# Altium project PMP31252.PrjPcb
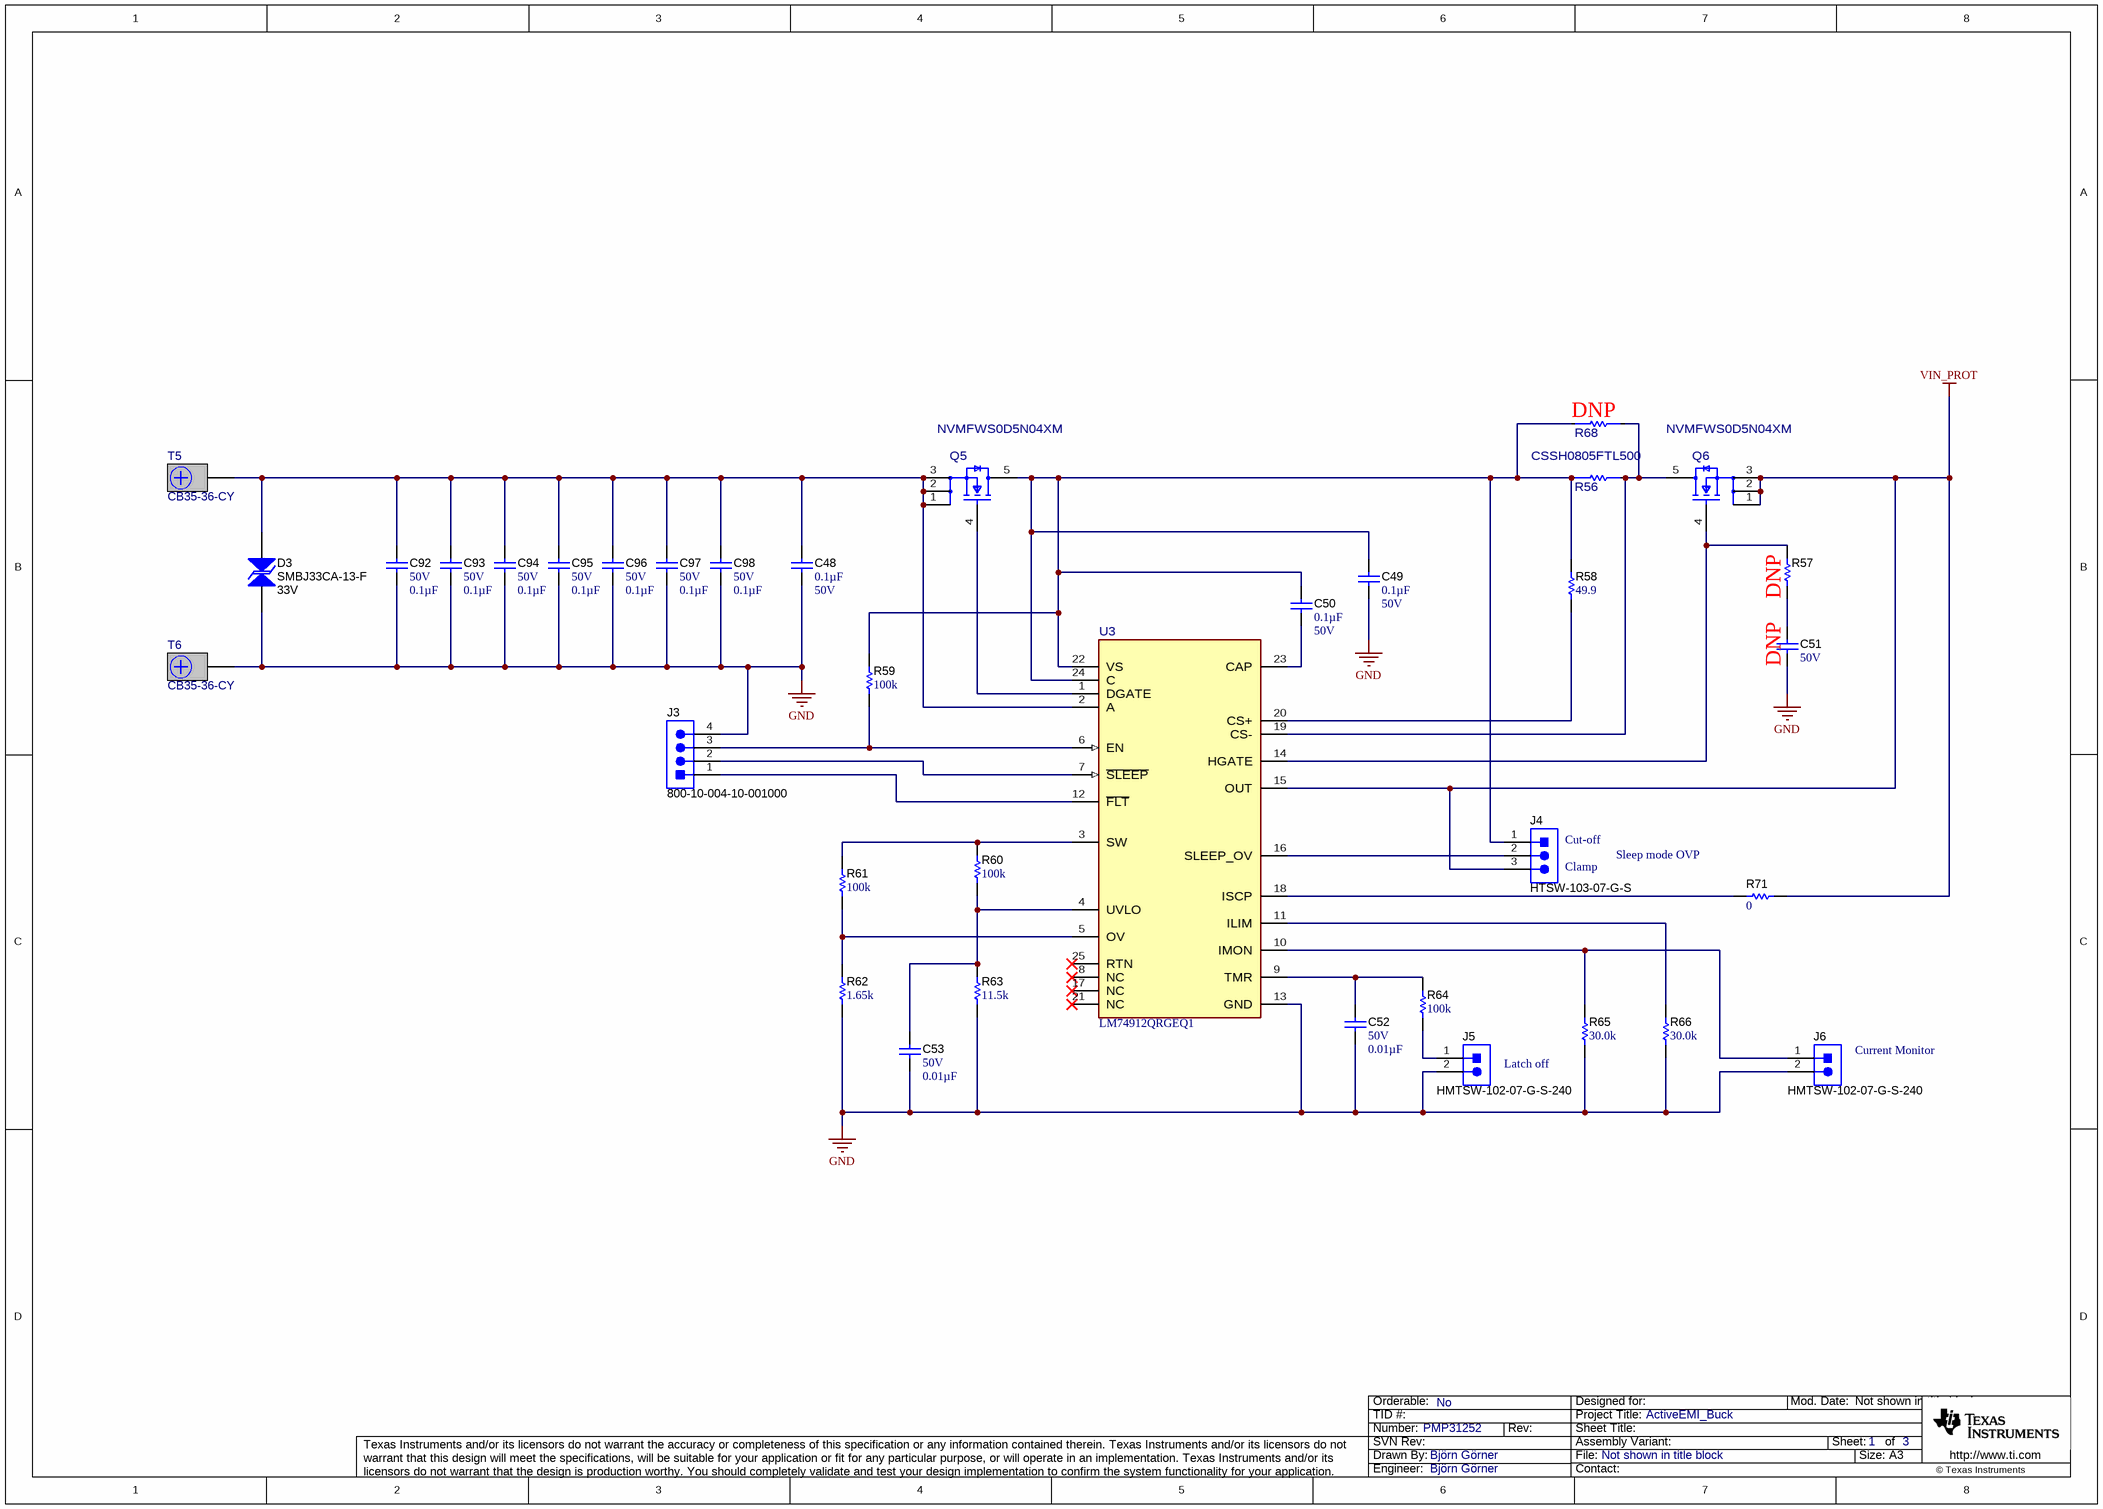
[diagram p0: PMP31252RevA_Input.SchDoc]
DrawnBy: Björn Görner; EVM_orderable: No; PRJ_Engineer: Björn Görner; PRJ_Number: E1; PRJ_Number: PMP31252; PRJ_Title: ActiveEMI_Buck
3 sheets, 218 parts. Net scope: global (net labels, ports and power ports of the same name join across sheets).
Board file: PMP31252.PcbDoc
Sheets:
  PMP31252RevA_Input.SchDoc
  PMP31252RevA_M.SchDoc
  PMP31252RevA_S.SchDoc

## Sheet PMP31252RevA_Input.SchDoc
size A3; Date: Not shown in title block; ApprovedBy: Not shown in title block; CheckedBy: Not shown in title block; Author: Not shown in title block; CompanyName: Not shown in title block; Engineer: Not shown in title block; Organization: Not shown in title block; Address1: Not shown in title block; Address2: Not shown in title block; Address3: Not shown in title block; Address4: Not shown in title block; DocumentNumber: 1; Revision: Use project parameter SCH_Rev; SheetNumber: 1; SheetTotal: 3; PageSetup: Record=PageOptions¦CenterHorizontal=True¦CenterVertical=True¦PrintScale=0.69¦XCorrection=1.00¦YCorrection=1.00¦PrintKind=0¦BorderSize=5000000¦LeftOffset=0¦BottomOffset=0¦Orientation=2¦PaperLength=1000¦PaperWidth=1000¦Scale=100¦PaperSource=15¦PrintQuality=600¦MediaType=1¦DitherType=10¦PaperKind=Letter¦PrintScaleMode=1

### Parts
C48  ValueDisplayed: 0.1µF  VDC_V: 50V  [0402]  (hidden comment: CGA2B3X7R1H104K050BD)
C49  ValueDisplayed: 0.1µF  VDC_V: 50V  [0402]  (hidden comment: CGA2B3X7R1H104K050BD)
C50  ValueDisplayed: 0.1µF  VDC_V: 50V  [0402]  (hidden comment: CGA2B3X7R1H104K050BD)
C51  VDC_V: 50V  [0402]  (hidden comment: CGA2B3X8R1H103K050BB)
C52  VDC_V: 50V  ValueDisplayed: 0.01µF  [0402]  (hidden comment: CGA2B3X8R1H103K050BB)
C53  VDC_V: 50V  ValueDisplayed: 0.01µF  [0402]  (hidden comment: CGA2B3X8R1H103K050BB)
C92  VDC_V: 50V  ValueDisplayed: 0.1µF  [0603]  (hidden comment: CGA3E3X8R1H104K080AE)
C93  VDC_V: 50V  ValueDisplayed: 0.1µF  [0603]  (hidden comment: CGA3E3X8R1H104K080AE)
C94  VDC_V: 50V  ValueDisplayed: 0.1µF  [0603]  (hidden comment: CGA3E3X8R1H104K080AE)
C95  VDC_V: 50V  ValueDisplayed: 0.1µF  [0603]  (hidden comment: CGA3E3X8R1H104K080AE)
C96  VDC_V: 50V  ValueDisplayed: 0.1µF  [0603]  (hidden comment: CGA3E3X8R1H104K080AE)
C97  VDC_V: 50V  ValueDisplayed: 0.1µF  [0603]  (hidden comment: CGA3E3X8R1H104K080AE)
C98  VDC_V: 50V  ValueDisplayed: 0.1µF  [0603]  (hidden comment: CGA3E3X8R1H104K080AE)
D3  SMBJ33CA-13-F  value 33V  [SMB-Bi]
J3  800-10-004-10-001000  [Mill-Max_800-10-004-10-001000]
J4  HTSW-103-07-G-S  [Samtec_HTSW-103-07-G-S]
J5  HMTSW-102-07-G-S-240  [SAMTEC_HMTSW-102-07-G-S-240]
J6  HMTSW-102-07-G-S-240  [SAMTEC_HMTSW-102-07-G-S-240]
Q5  NVMFWS0D5N04XM  [FP-BUK9J0R9-40H_SOT1023-MFG]
Q6  NVMFWS0D5N04XM  [FP-BUK9J0R9-40H_SOT1023-MFG]
R56  CSSH0805FTL500  [FP-CSSH0805FTL500_0805-MFG]
R57  RMCF0402JT100R  [0402]  (value not drawn)
R58  ValueDisplayed: 49.9  [0402]  (hidden comment: ERJ-2RKF49R9X)
R59  ValueDisplayed: 100k  [0402]  (hidden comment: RMCF0402FT100K)
R60  ValueDisplayed: 100k  [0402]  (hidden comment: RMCF0402FT100K)
R61  ValueDisplayed: 100k  [0402]  (hidden comment: RMCF0402FT100K)
R62  ValueDisplayed: 1.65k  [0402]  (hidden comment: CRCW04021K65FKED)
R63  ValueDisplayed: 11.5k  [0402]  (hidden comment: CRCW040211K5FKED)
R64  ValueDisplayed: 100k  [0402]  (hidden comment: CRCW0402100KFKED)
R65  ValueDisplayed: 30.0k  [0402]  (hidden comment: CRCW040230K0FKED)
R66  ValueDisplayed: 30.0k  [0402]  (hidden comment: CRCW040230K0FKED)
R68  HCS2512FT1L00  [FP-HCS2512FT1L00_2512-MFG]  (value not drawn)
R71  ValueDisplayed: 0  [0402]  (hidden comment: ERJ-2GE0R00X)
T5  CB35-36-CY  [CB35-36-CY]
T6  CB35-36-CY  [CB35-36-CY]
U3  LM74912QRGEQ1  [RGE0024T-MFG]

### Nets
GND: C48.2 C49.2 C51.2 C52.2 C53.2 C92.2 C93.2 C94.2 C95.2 C96.2 C97.2 C98.2 D3.1 J3.4 J5.2 J6.2 R62.1 R63.1 R65.1 R66.1 T6.1 U3.13(GND)
VIN_PROT: J4.3 Q6.1(S) Q6.2(S) Q6.3(S) R71.2 U3.15(OUT)
NetC48_1: C48.1 C92.1 C93.1 C94.1 C95.1 C96.1 C97.1 C98.1 D3.2 Q5.1(S) Q5.2(S) Q5.3(S) T5.1 U3.2(A)
NetC49_1: C49.1 C50.1 J4.1 Q5.5(D) R56.1 R58.2 R59.2 R68.1 U3.22(VS) U3.24(C)
NetC50_2: C50.2 U3.23(CAP)
NetC51_1: C51.1 R57.1
NetC52_1: C52.1 R64.2 U3.9(TMR)
NetC53_1: C53.1 R60.1 R63.2 U3.4(UVLO)
NetJ3_1: J3.1 U3.12(~{FLT})
NetJ3_2: J3.2 U3.7(~{SLEEP})
NetJ3_3: J3.3 R59.1 U3.6(EN)
NetJ4_2: J4.2 U3.16(SLEEP_OV)
NetJ5_1: J5.1 R64.1
NetJ6_1: J6.1 R65.2 U3.10(IMON)
NetQ5_4: Q5.4(G) U3.1(DGATE)
NetQ6_4: Q6.4(G) R57.2 U3.14(HGATE)
NetQ6_5: Q6.5(D) R56.2 R68.2 U3.19(CS-)
NetR58_1: R58.1 U3.20(CS+)
NetR60_2: R60.2 R61.2 U3.3(SW)
NetR61_1: R61.1 R62.2 U3.5(OV)
NetR66_2: R66.2 U3.11(ILIM)
NetR71_1: R71.1 U3.18(ISCP)

Not connected (* = marked no-connect by the designer): U3 8(NC)* 17(NC)* 21(NC)* 25(RTN)*

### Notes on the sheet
- (near R68) DNP
- (near R57) DNP
- (near C51) DNP
- (near J4) Cut-off
- Sleep mode OVP
- (near J4) Clamp
- (near J6) Current Monitor
- Latch off

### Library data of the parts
C48-C50 = CMP-0084548-1: CAP, CERM, 0.1 µF, 50 V,+/- 10%, X7R, AEC-Q200 Grade 1, 0402; Manufacturer: TDK; SizeZ_mm: 0.6; TaMax_C: 125°C; Cap_F: 100nF; Polarized: N; SizeX_mm: 1; Value: 0.1uF; AEC Category: Q200; TaMin_C: -55°C; SizeArea_mm2: 0.5; SizeAreaWB_mm2: 3; U/M: EA; AEC Qualified: Y
C51 = CMP-0078224-1: CAP, CERM, 0.01 µF, 50 V,+/- 10%, X8R, AEC-Q200 Grade 0, 0402; Manufacturer: TDK; TaMin_C: -55°C; Polarized: N; SizeAreaWB_mm2: 3; U/M: EA; Value: 0.01uF; TaMax_C: 150°C; SizeZ_mm: 0.6; SizeX_mm: 1; SizeY_mm: 0.5; AEC Qualified: Y; Cap_F: 10nF; AEC Grade: 0; AEC Category: Q200; ValueDisplayed: 0.01µF
C52 C53 = CMP-0078224-1: CAP, CERM, 0.01 µF, 50 V,+/- 10%, X8R, AEC-Q200 Grade 0, 0402; Manufacturer: TDK; TaMin_C: -55°C; Polarized: N; SizeAreaWB_mm2: 3; U/M: EA; Value: 0.01uF; TaMax_C: 150°C; SizeZ_mm: 0.6; SizeX_mm: 1; SizeY_mm: 0.5; AEC Qualified: Y; Cap_F: 10nF; AEC Grade: 0; AEC Category: Q200
C92-C98 = CMP-0079911-1: CAP, CERM, 0.1 µF, 50 V,+/- 10%, X8R, AEC-Q200 Grade 0, 0603; Manufacturer: TDK; Cap_F: 100nF; SizeAreaWB_mm2: 4.68; SizeArea_mm2: 1.28; AEC Qualified: Y; AEC Category: Q200; Value: 0.1uF; TaMax_C: 150°C; SizeZ_mm: 1; AEC Grade: 0; Polarized: N; TaMin_C: -55°C; SizeY_mm: 0.8; U/M: EA; SizeX_mm: 1.6
D3 = CMP-0005564-3: Diode, TVS, Bi, 33 V, SMB; Manufacturer: Diodes Inc.; SizeX_mm: 5.6; Ppk: 600W; SizeAreaWB_mm2: 44.156; SizeZ_mm: 2.6; SizeArea_mm2: 21.336; SizeY_mm: 3.81; AEC Category: Q101
J3 = CMP-0055087-1: Header, 100mil, 4x1, TH; Manufacturer: Mill-Max; CT: FALSE; CNHeader: TRUE
J4 = CMP-0075484-1: Header, 100mil, 3x1, Gold, TH; Manufacturer: Samtec; Green_REACh: Passed; CT: False; Green_Lifecycle: Active; CNHeader: True
J5 J6 = CMP-0075500-1: Header, 100mil, 2x1, Gold, TH; Manufacturer: Samtec; Green_REACh: Passed; CT: False; Green_Lifecycle: Active; CNHeader: True
Q5 Q6 = CMP-0086636-1: N-channel 40 V, 0.9 mΩ logic level MOSFET in LFPAK56E; PartNumber: BUK9J0R9-40H; Manufacturer: Nexperia; VdsMax_V: 40V; ChMode: False; Rdson45_ohm: 970µ; AEC Qualified: Yes; QgTyp_nC: 120nC @ 10V; IdsMax_A: 220A; SizeZ_mm: 1.25mm
R56 = CMP-0093189-1: 500 µOhms ±1% 1W Chip Resistor 0805 (2012 Metric) Automotive AEC-Q200, Current Sense Metal Element; Manufacturer: Stackpole Electronics; AEC Qualified: Yes; SizeZ_mm: 0.8mm; TempCo: 100ppm/°C; AEC Grade: Grade 0; Res_ohm: 500µ; Value: 500µ
R57 = CMP-0026763-1: RES, 100, 1%, 0.063 W, AEC-Q200 Grade 0, 0402; Manufacturer: Stackpole Electronics Inc; Power_W: 63mW; TempCo: 100 ppm/C; Value_Code: 100R; U/M: EA; Value: 100; EIA_Code: E96; SizeX_mm: 1; SizeY_mm: 0.5; SizeZ_mm: 0.6; Value2: 0.063W; AEC Qualified: Y; AEC Grade: 0; AEC Category: Q200
R58 = CMP-0026703-1: RES, 49.9, 1%, 0.1 W, AEC-Q200 Grade 0, 0402; Manufacturer: Panasonic; Power_W: 100mW; TempCo: 100 ppm/C; Value_Code: 49R9; U/M: EA; Value: 49.9; EIA_Code: E96; SizeX_mm: 1; SizeY_mm: 0.5; SizeZ_mm: 0.6; Value2: 0.1W; AEC Qualified: Y; VDC_V: 50V; AEC Grade: 0; AEC Category: Q200
R59-R61 = CMP-0026753-1: RES, 100 k, 1%, 0.063 W, AEC-Q200 Grade 0, 0402; Manufacturer: Stackpole Electronics Inc; Power_W: 63mW; TempCo: 100 ppm/C; U/M: EA; Value: 100k; EIA_Code: E96; SizeX_mm: 1; SizeY_mm: 0.5; SizeZ_mm: 0.6; Value2: 0.063W; AEC Qualified: Y; VDC_V: 50V; AEC Grade: 0; AEC Category: Q200
R62 = CMP-0026092-3: RES, 1.65 k, 1%, 0.063 W, AEC-Q200 Grade 0, 0402; Manufacturer: Vishay-Dale; Power_W: 63mW; TempCo: 100 ppm/C; Value_Code: 1k65; Value: 1.65k; EIA_Code: E96; SizeX_mm: 1; SizeY_mm: 0.5; SizeZ_mm: 0.6; Value2: 0.063W; AEC Qualified: Y; VDC_V: 50V; AEC Category: Q200; AEC Grade: 0
R63 = CMP-0025977-3: RES, 11.5 k, 1%, 0.063 W, AEC-Q200 Grade 0, 0402; Manufacturer: Vishay-Dale; Power_W: 63mW; TempCo: 100 ppm/C; Value_Code: 11k5; Value: 11.5k; EIA_Code: E96; SizeX_mm: 1; SizeY_mm: 0.5; SizeZ_mm: 0.6; Value2: 0.063W; AEC Qualified: Y; VDC_V: 50V; AEC Category: Q200; AEC Grade: 0
R64 = CMP-0025950-3: RES, 100 k, 1%, 0.063 W, AEC-Q200 Grade 0, 0402; Manufacturer: Vishay-Dale; Power_W: 63mW; TempCo: 100 ppm/C; Value: 100k; EIA_Code: E96; SizeX_mm: 1; SizeY_mm: 0.5; SizeZ_mm: 0.6; Value2: 0.063W; AEC Qualified: Y; VDC_V: 50V; AEC Category: Q200; AEC Grade: 0
R65 R66 = CMP-0078244-2: RES, 30.0 k, 1%, 0.063 W, AEC-Q200 Grade 0, 0402; Manufacturer: Vishay-Dale; Power_W: 63mW; Green_Lifecycle: Active; TempCo: 100 ppm/C; Value_Code: 30k0; Green_REACh: Passed; Value: 30.0k; Res_ohm: 30k; SizeX_mm: 1; SizeY_mm: 0.5; SizeZ_mm: 0.6; Value2: 0.063W; AEC Qualified: Y; VDC_V: 50V; AEC Grade: 0; AEC Category: Q200
R68 = CMP-0092536-1: 1 mOhms ±1% 3W Chip Resistor 2512 (6432 Metric) Automotive AEC-Q200, Current Sense, Moisture Resistant Metal Element; Manufacturer: Stackpole Electronics; AEC Qualified: Yes; AEC Grade: Grade 0; SizeZ_mm: 0.88mm; Value: 1m; TempCo: 100ppm/°C
R71 = CMP-0026992-3: RES, 0, 5%, 0.1 W, AEC-Q200 Grade 0, 0402; Manufacturer: Panasonic; Power_W: 100mW; TempCo: 600 ppm/C; Value_Code: 0000; Value: 0; EIA_Code: E24; SizeX_mm: 1; SizeY_mm: 0.5; SizeZ_mm: 0.6; Value2: 0.1W; AEC Qualified: Y; VDC_V: 50V; AEC Category: Q200; SizeAreaWB_mm2: 3
T5 T6 = CMP-0055442-1: Terminal 50A Lug; Manufacturer: Panduit; CNHeader: FALSE; Green_Lifecycle: Not Set; Cert_CULUS: Y; Green_REACh: Incomplete; Voltage_V: 600V; CompType: Screw Terminal; ContactFinish: Copper
U3 = CMP-0001363-1: Ideal Diode Controller with Integrated Short Circuit Protection with Fault Output; Manufacturer: Texas Instruments; SizeZ_mm: 1mm; AEC Qualified: Yes; AEC Grade: Grade 1; Max Supply Voltage: 65V; Min Supply Voltage: 3V; Nominal Supply Current: 550-600uA; Number Of Outputs: 1; Standoff Height: 0mm; TaMax_C: +125°C; TaMin_C: -40°C; TJmax_C: +150°C

## Sheet PMP31252RevA_M.SchDoc
size A3; Date: Not shown in title block; ApprovedBy: Not shown in title block; CheckedBy: Not shown in title block; Author: Not shown in title block; CompanyName: Not shown in title block; Engineer: Not shown in title block; Organization: Not shown in title block; Address1: Not shown in title block; Address2: Not shown in title block; Address3: Not shown in title block; Address4: Not shown in title block; DocumentNumber: 1; Revision: Use project parameter SCH_Rev; SheetNumber: 2; SheetTotal: 3; PageSetup: Record=PageOptions¦CenterHorizontal=True¦CenterVertical=True¦PrintScale=0.69¦XCorrection=1.00¦YCorrection=1.00¦PrintKind=0¦BorderSize=5000000¦LeftOffset=0¦BottomOffset=0¦Orientation=2¦PaperLength=1000¦PaperWidth=1000¦Scale=100¦PaperSource=15¦PrintQuality=600¦MediaType=1¦DitherType=10¦PaperKind=Letter¦PrintScaleMode=1
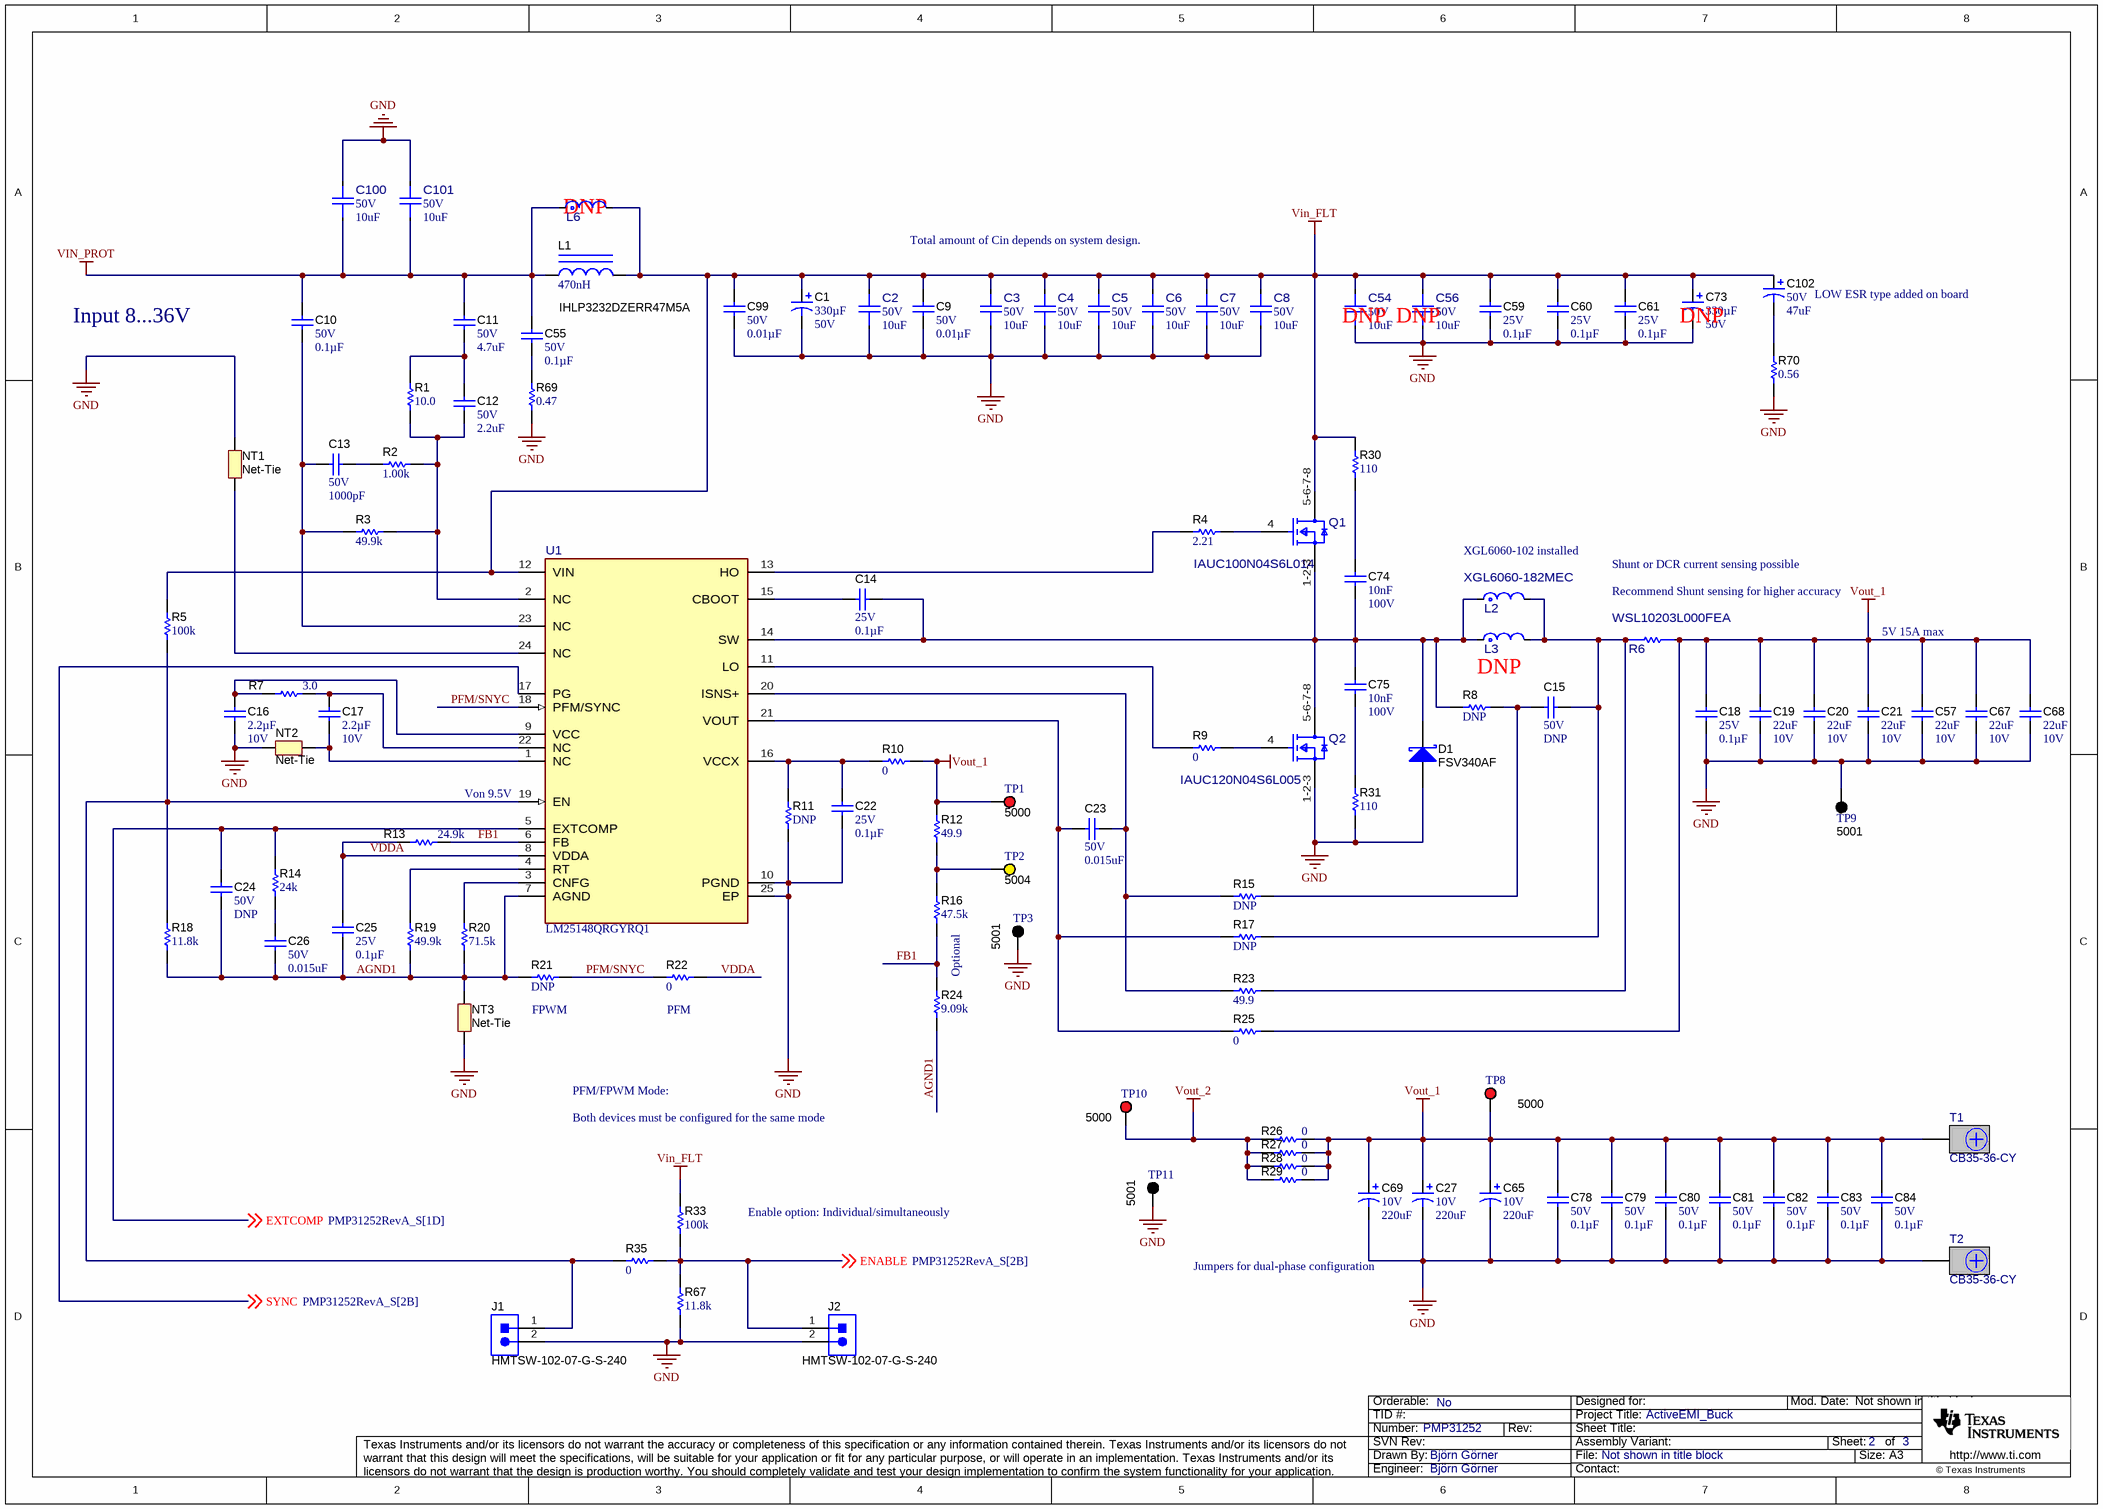
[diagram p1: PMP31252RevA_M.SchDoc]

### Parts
C1  ValueDisplayed: 330µF  VDC_V: 50V  [SM_RADIAL_G]  (hidden comment: EEE-FT1H331AP)
C2  VDC_V: 50V  ValueDisplayed: 10uF  [FP-GCM32EC71H106KA03L_1210-MFG]  (hidden comment: GCM32EC71H106KA03L)
C3  VDC_V: 50V  ValueDisplayed: 10uF  [FP-GCM32EC71H106KA03L_1210-MFG]  (hidden comment: GCM32EC71H106KA03L)
C4  VDC_V: 50V  ValueDisplayed: 10uF  [FP-GCM32EC71H106KA03L_1210-MFG]  (hidden comment: GCM32EC71H106KA03L)
C5  VDC_V: 50V  ValueDisplayed: 10uF  [FP-GCM32EC71H106KA03L_1210-MFG]  (hidden comment: GCM32EC71H106KA03L)
C6  VDC_V: 50V  ValueDisplayed: 10uF  [FP-GCM32EC71H106KA03L_1210-MFG]  (hidden comment: GCM32EC71H106KA03L)
C7  VDC_V: 50V  ValueDisplayed: 10uF  [FP-GCM32EC71H106KA03L_1210-MFG]  (hidden comment: GCM32EC71H106KA03L)
C8  VDC_V: 50V  ValueDisplayed: 10uF  [FP-GCM32EC71H106KA03L_1210-MFG]  (hidden comment: GCM32EC71H106KA03L)
C9  VDC_V: 50V  ValueDisplayed: 0.01µF  [0402]  (hidden comment: CGA2B3X8R1H103K050BB)
C10  VDC_V: 50V  ValueDisplayed: 0.1µF  [0603]  (hidden comment: CGA3E3X8R1H104K080AE)
C11  VDC_V: 50V  ValueDisplayed: 4.7uF  [1210_280]  (hidden comment: CGA6P3X7R1H475K250AB)
C12  VDC_V: 50V  ValueDisplayed: 2.2uF  [1206_180]  (hidden comment: GCM31CR71H225KA55L)
C13  VDC_V: 50V  ValueDisplayed: 1000pF  [0402]  (hidden comment: GCM155R71H102KA37D)
C14  VDC_V: 25V  ValueDisplayed: 0.1µF  [0402]  (hidden comment: CGA2B3X7R1E104K050BB)
C15  VDC_V: 50V  ValueDisplayed: DNP  [0402]  (hidden comment: GCM155R71H104KE02D)
C16  Cap_F: 2.2µF  VDC_V: 10V  [0603]  (hidden comment: GRM188R71A225KE15J)
C17  Cap_F: 2.2µF  VDC_V: 10V  [0603]  (hidden comment: GRM188R71A225KE15J)
C18  VDC_V: 25V  ValueDisplayed: 0.1µF  [0402]  (hidden comment: CGA2B3X7R1E104K050BB)
C19  ValueDisplayed: 22uF  VDC_V: 10V  [1206_180]  (hidden comment: GCM31CR71A226KE02L)
C20  ValueDisplayed: 22uF  VDC_V: 10V  [1206_180]  (hidden comment: GCM31CR71A226KE02L)
C21  ValueDisplayed: 22uF  VDC_V: 10V  [1206_180]  (hidden comment: GCM31CR71A226KE02L)
C22  VDC_V: 25V  ValueDisplayed: 0.1µF  [0402]  (hidden comment: CGA2B3X7R1E104K050BB)
C23  VDC_V: 50V  ValueDisplayed: 0.015uF  [0402]  (hidden comment: CGA2B3X7R1H153K050BB)
C24  VDC_V: 50V  ValueDisplayed: DNP  [0402]  (hidden comment: CGA2B2C0G1H151J050BA)
C25  VDC_V: 25V  ValueDisplayed: 0.1µF  [0402]  (hidden comment: CGA2B3X7R1E104K050BB)
C26  VDC_V: 50V  ValueDisplayed: 0.015uF  [0402]  (hidden comment: CGA2B3X7R1H153K050BB)
C27  VDC_V: 10V  ValueDisplayed: 220uF  [7343-31]  (hidden comment: T598D227M010ATE025)
C54  VDC_V: 50V  ValueDisplayed: 10uF  [FP-GCM32EC71H106KA03L_1210-MFG]  (hidden comment: GCM32EC71H106KA03L)
C55  VDC_V: 50V  ValueDisplayed: 0.1µF  [0603]  (hidden comment: CGA3E3X8R1H104K080AE)
C56  VDC_V: 50V  ValueDisplayed: 10uF  [FP-GCM32EC71H106KA03L_1210-MFG]  (hidden comment: GCM32EC71H106KA03L)
C57  ValueDisplayed: 22uF  VDC_V: 10V  [1206_180]  (hidden comment: GCM31CR71A226KE02L)
C59  VDC_V: 25V  ValueDisplayed: 0.1µF  [0402]  (hidden comment: CGA2B3X7R1E104K050BB)
C60  VDC_V: 25V  ValueDisplayed: 0.1µF  [0402]  (hidden comment: CGA2B3X7R1E104K050BB)
C61  VDC_V: 25V  ValueDisplayed: 0.1µF  [0402]  (hidden comment: CGA2B3X7R1E104K050BB)
C65  VDC_V: 10V  ValueDisplayed: 220uF  [7343-31]  (hidden comment: T598D227M010ATE025)
C67  ValueDisplayed: 22uF  VDC_V: 10V  [1206_180]  (hidden comment: GCM31CR71A226KE02L)
C68  ValueDisplayed: 22uF  VDC_V: 10V  [1206_180]  (hidden comment: GCM31CR71A226KE02L)
C69  VDC_V: 10V  ValueDisplayed: 220uF  [7343-31]  (hidden comment: T598D227M010ATE025)
C73  ValueDisplayed: 330µF  VDC_V: 50V  [SM_RADIAL_G]  (hidden comment: EEE-FT1H331AP)
C74  Cap_F: 10nF  VDC_V: 100V  [0805_HV]  (hidden comment: GRM21BR72A103KA01L)
C75  Cap_F: 10nF  VDC_V: 100V  [0805_HV]  (hidden comment: GRM21BR72A103KA01L)
C78  VDC_V: 50V  ValueDisplayed: 0.1µF  [0603]  (hidden comment: CGA3E3X8R1H104K080AE)
C79  VDC_V: 50V  ValueDisplayed: 0.1µF  [0603]  (hidden comment: CGA3E3X8R1H104K080AE)
C80  VDC_V: 50V  ValueDisplayed: 0.1µF  [0603]  (hidden comment: CGA3E3X8R1H104K080AE)
C81  VDC_V: 50V  ValueDisplayed: 0.1µF  [0603]  (hidden comment: CGA3E3X8R1H104K080AE)
C82  VDC_V: 50V  ValueDisplayed: 0.1µF  [0603]  (hidden comment: CGA3E3X8R1H104K080AE)
C83  VDC_V: 50V  ValueDisplayed: 0.1µF  [0603]  (hidden comment: CGA3E3X8R1H104K080AE)
C84  VDC_V: 50V  ValueDisplayed: 0.1µF  [0603]  (hidden comment: CGA3E3X8R1H104K080AE)
C99  VDC_V: 50V  ValueDisplayed: 0.01µF  [0402]  (hidden comment: CGA2B3X8R1H103K050BB)
C100  VDC_V: 50V  ValueDisplayed: 10uF  [FP-GCM32EC71H106KA03L_1210-MFG]  (hidden comment: GCM32EC71H106KA03L)
C101  VDC_V: 50V  ValueDisplayed: 10uF  [FP-GCM32EC71H106KA03L_1210-MFG]  (hidden comment: GCM32EC71H106KA03L)
C102  VDC_V: 50V  ValueDisplayed: 47uF  [SM_RADIAL_D8]  (hidden comment: EEE-FK1H470XP)
D1  FSV340AF  [SMAF]
J1  HMTSW-102-07-G-S-240  [SAMTEC_HMTSW-102-07-G-S-240]
J2  HMTSW-102-07-G-S-240  [SAMTEC_HMTSW-102-07-G-S-240]
L1  IHLP3232DZERR47M5A  ValueDisplayed: 470nH  [IHLP-3232DZ]
L2  XGL6060-182MEC  [FP-XGL6060-472MEC_SMT2_6MM51_6MM71-MFG]
L3  XGL1010-801MEC  [FP-XGL1060-332MEC_SMT2_10MM0_11MM3-MFG]  (value not drawn)
L6  XGL1010-801MEC  [FP-XGL1060-332MEC_SMT2_10MM0_11MM3-MFG]  (value not drawn)
NT1  Net-Tie  [Net-Tie_10milWide_30milLong]  (net tie, no BOM)
NT2  Net-Tie  [Net-Tie_10milWide_30milLong]  (net tie, no BOM)
NT3  Net-Tie  [Net-Tie_10milWide_30milLong]  (net tie, no BOM)
Q1  IAUC100N04S6L014  [FP-IAUC120N04S6N009ATMA1_TDSON8-MFG]
Q2  IAUC120N04S6L005  [FP-IAUC120N04S6N009ATMA1_TDSON8-MFG]
R1  ValueDisplayed: 10.0  [0603]  (hidden comment: CRCW060310R0FKEA)
R2  ValueDisplayed: 1.00k  [0402]  (hidden comment: ERA-2APB102X)
R3  ValueDisplayed: 49.9k  [0402]  (hidden comment: ERJ-2RKF4992X)
R4  ValueDisplayed: 2.21  [0603]  (hidden comment: CRCW06032R21FKEA)
R5  ValueDisplayed: 100k  [0402]  (hidden comment: CRCW0402100KFKED)
R6  WSL10203L000FEA  [FP-WSL10203L000FEA_1020-MFG]
R7  ValueDisplayed: 3.0  [0402]  (hidden comment: CRCW04023R00JNED)
R8  ValueDisplayed: DNP  [0603]  (hidden comment: CRCW06030000Z0EA)
R9  ValueDisplayed: 0  [0603]  (hidden comment: CRCW06030000Z0EA)
R10  ValueDisplayed: 0  [0402]  (hidden comment: ERJ-2GE0R00X)
R11  ValueDisplayed: DNP  [0402]  (hidden comment: ERJ-2GE0R00X)
R12  ValueDisplayed: 49.9  [0402]  (hidden comment: ERJ-2RKF49R9X)
R13  ValueDisplayed: 24.9k  [0402]  (hidden comment: CRCW040224K9FKED)
R14  ValueDisplayed: 24k  [0402]  (hidden comment: CRCW040224K0JNED)
R15  ValueDisplayed: DNP  [0402]  (hidden comment: ERJ-2GE0R00X)
R16  ValueDisplayed: 47.5k  [0402]  (hidden comment: CRCW040247K5FKED)
R17  ValueDisplayed: DNP  [0402]  (hidden comment: ERJ-2GE0R00X)
R18  ValueDisplayed: 11.8k  [0402]  (hidden comment: CRCW040211K8FKED)
R19  ValueDisplayed: 49.9k  [0402]  (hidden comment: ERJ-2RKF4992X)
R20  ValueDisplayed: 71.5k  [0402]  (hidden comment: CRCW040271K5FKED)
R21  ValueDisplayed: DNP  [0402]  (hidden comment: ERJ-2GE0R00X)
R22  ValueDisplayed: 0  [0402]  (hidden comment: ERJ-2GE0R00X)
R23  ValueDisplayed: 49.9  [0402]  (hidden comment: ERJ-2RKF49R9X)
R24  ValueDisplayed: 9.09k  [0402]  (hidden comment: CRCW04029K09FKED)
R25  ValueDisplayed: 0  [0402]  (hidden comment: ERJ-2GE0R00X)
R26  ValueDisplayed: 0  [RM1206]  (hidden comment: D55342E07B000ATTR)
R27  ValueDisplayed: 0  [RM1206]  (hidden comment: D55342E07B000ATTR)
R28  ValueDisplayed: 0  [RM1206]  (hidden comment: D55342E07B000ATTR)
R29  ValueDisplayed: 0  [RM1206]  (hidden comment: D55342E07B000ATTR)
R30  ValueDisplayed: 110  [1206]  (hidden comment: RC1206FR-07110RL)
R31  ValueDisplayed: 110  [1206]  (hidden comment: RC1206FR-07110RL)
R33  ValueDisplayed: 100k  [0402]  (hidden comment: CRCW0402100KFKED)
R35  ValueDisplayed: 0  [0402]  (hidden comment: ERJ-2GE0R00X)
R67  ValueDisplayed: 11.8k  [0402]  (hidden comment: CRCW040211K8FKED)
R69  ValueDisplayed: 0.47  [0603]  (hidden comment: ERJ-3RQFR47V)
R70  ValueDisplayed: 0.56  [0805_HV]  (hidden comment: ERJ-6RQFR56V)
T1  CB35-36-CY  [CB35-36-CY]
T2  CB35-36-CY  [CB35-36-CY]
TP1  5000  [Keystone5000]
TP2  5004  [Keystone5004]
TP3  5001  [Keystone5001]
TP8  5000  [Keystone5000]
TP9  5001  [Keystone5001]
TP10  5000  [Keystone5000]
TP11  5001  [Keystone5001]
U1  LM25148QRGYRQ1  [RGY0024E-MFG]

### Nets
GND: C1.2(-) C2.1 C3.1 C4.1 C5.1 C6.1 C7.1 C8.1 C9.2 C16.2 C18.2 C19.2 C20.2 C21.2 C22.2 C27.2(-) C54.1 C56.1 C57.2 C59.2 C60.2 C61.2 C65.2(-) C67.2 C68.2 C69.2(-) C73.2(-) C78.2 C79.2 C80.2 C81.2 C82.2 C83.2 C84.2 C99.2 C100.2 C101.2 D1.2(A) J1.2 J2.2 NT1.2 NT2.2 NT3.2 Q2.1-2-3(S) R11.1 R31.1 R67.1 R69.1 R70.1 T2.1 TP3.1 TP9.1 TP11.1 U1.10(PGND) U1.25(EP)
Vin_FLT: C1.1(+) C2.2 C3.2 C4.2 C5.2 C6.2 C7.2 C8.2 C9.1 C54.2 C56.2 C59.1 C60.1 C61.1 C73.1(+) C99.1 C102.1(+) L1.2 L6.2 Q1.5-6-7-8(D) R5.2 R30.2 R33.2 U1.12(VIN)
VIN_PROT: C10.1 C11.1 C55.1 C100.1 C101.1 L1.1 L6.1
Vout_1: C18.1 C19.1 C20.1 C21.1 C27.1(+) C57.1 C65.1(+) C67.1 C68.1 C69.1(+) C78.1 C79.1 C80.1 C81.1 C82.1 C83.1 C84.1 R6.2 R10.2 R12.2 R25.2 R26.2 R27.2 R28.2 R29.2 T1.1 TP1.1 TP8.1
Vout_2: R26.1 R27.1 R28.1 R29.1 TP10.1
AGND1: C24.2 C25.2 C26.2 NT3.1 R18.1 R19.1 R20.1 R21.1 R24.1 U1.7(AGND)
ENABLE: J2.1 R33.1 R35.2 R67.2 ; off-sheet ENABLE
EXTCOMP: C24.1 R14.2 U1.5(EXTCOMP) ; off-sheet EXTCOMP
FB1: R13.1 R16.1 R24.2 U1.6(FB)
PFM/SNYC: R21.2 R22.2 U1.18(PFM/SYNC)
SYNC: U1.17(PG) ; off-sheet SYNC
VDDA: C25.1 R13.2 R22.1 U1.8(VDDA)
NetC10_2: C10.2 C13.2 R3.1 U1.23(NC)
NetC11_2: C11.2 C12.1 R1.2
NetC12_2: C12.2 R1.1 R2.2 R3.2 U1.2(NC)
NetC13_1: C13.1 R2.1
NetC14_1: C14.1 C74.2 C75.1 D1.1(K) L2.1 L3.1 Q1.1-2-3(S) Q2.5-6-7-8(D) R8.1 U1.14(SW)
NetC14_2: C14.2 U1.15(CBOOT)
NetC15_1: C15.1 L2.2 L3.2 R6.1 R17.2 R23.2
NetC15_2: C15.2 R8.2 R15.2
NetC16_1: C16.1 R7.1 U1.9(VCC)
NetC17_1: C17.1 R7.2 U1.22(NC)
NetC17_2: C17.2 NT2.1 U1.1(NC)
NetC22_1: C22.1 R10.1 R11.2 U1.16(VCCX)
NetC23_1: C23.1 R15.1 R23.1 U1.20(ISNS+)
NetC23_2: C23.2 R17.1 R25.1 U1.21(VOUT)
NetC26_1: C26.1 R14.1
NetC55_2: C55.2 R69.2
NetC74_1: C74.1 R30.1
NetC75_2: C75.2 R31.2
NetC102_2: C102.2(-) R70.2
NetJ1_1: J1.1 R5.1 R18.2 R35.1 U1.19(EN)
NetNT1_1: NT1.1 U1.24(NC)
NetQ1_4: Q1.4(G) R4.2
NetQ2_4: Q2.4(G) R9.2
NetR4_1: R4.1 U1.13(HO)
NetR9_1: R9.1 U1.11(LO)
NetR12_1: R12.1 R16.2 TP2.1
NetR19_2: R19.2 U1.4(RT)
NetR20_2: R20.2 U1.3(CNFG)

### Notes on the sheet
- (near L6) DNP
- Total amount of Cin depends on system design.
- (near C102) LOW ESR type added on board
- Input 8...36V
- (near C54) DNP
- (near C56) DNP
- (near C73) DNP
- (near L2) XGL6060-102 installed
- Shunt or DCR current sensing possible
- (near R6) Recommend Shunt sensing for higher accuracy
- 5V 15A max
- DNP
- Von 9.5V
- (near U1) 440kHz
- Optional
- (near R21) FPWM
- (near R22) PFM
- PFM/FPWM Mode:
- Both devices must be configured for the same mode
- Enable option: Individual/simultaneously
- Jumpers for dual-phase configuration

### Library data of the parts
C1 C73 = CMP-0860442-1: CAP, AL, 330 µF, 50 V, +/- 20%, 0.12 ohm, AEC-Q200 Grade 2, SMD; Manufacturer: Panasonic; ESR_ohm: 0.12; CompType: Capacitor; U/M: EA; AEC Qualified: Y; TaMax_C: 105°C; Green_Lifecycle: Active; SizeY_mm: 10.3; SizeZ_mm: 10.2; Value: 330uF; AEC Grade: 2; TaMin_C: -55°C; Green_REACh: Passed; SizeArea_mm2: 123.6; AEC Category: Q200; Cap_Case: 10x10.2mm; SizeAreaWB_mm2: 172.2; SizeX_mm: 12
C2-C8 C54 C56 C100 C101 = CMP-0092251-1: Ceramic Capacitor for Automotive 10uF ±10% 50VDC X7S 1210 Embossed T/R; Manufacturer: Murata; AEC Grade: Grade 1; TempCo: 22%; AEC Qualified: Yes; Cap_F: 10µF; SizeZ_mm: 2.7mm; Value: 10µF
C9 C99 = CMP-0078224-1: as C52 on sheet PMP31252RevA_Input
C10 C55 C78-C84 = CMP-0079911-1: as C92 on sheet PMP31252RevA_Input
C11 = CMP-0009162-2: CAP, CERM, 4.7 uF, 50 V, +/- 10%, X7R, AEC-Q200 Grade 1, 1210; Manufacturer: TDK; TaMin_C: -55°C; ESR_ohm: 3.166m; Polarized: N; SizeAreaWB_mm2: 14.7; Value1: 0.003166 ohm; U/M: EA; Value: 4.7uF; TaMax_C: 125°C; SizeZ_mm: 2.8; SizeX_mm: 3.2; SizeY_mm: 2.5; SizeArea_mm2: 8; AEC Qualified: Y; Cap_F: 4.7µF; IRMS_A: 4.1331A; AEC Grade: 1; AEC Category: Q200
C12 = CMP-0008814-2: CAP, CERM, 2.2 uF, 50 V, +/- 10%, X7R, AEC-Q200 Grade 1, 1206; Manufacturer: MuRata; TaMin_C: -55°C; Polarized: N; SizeAreaWB_mm2: 10.92; Value1: Unknown; U/M: EA; Value: 2.2uF; TaMax_C: 125°C; SizeZ_mm: 1.8; SizeX_mm: 3.2; SizeY_mm: 1.6; Cap_Case: 1206; SizeArea_mm2: 5.12; AEC Qualified: Y; Cap_F: 2.2µF; AEC Grade: 1; AEC Category: Q200
C13 = CMP-0006354-2: CAP, CERM, 1000 pF, 50 V, +/- 10%, X7R, AEC-Q200 Grade 1, 0402; Manufacturer: MuRata; TaMin_C: -55°C; Polarized: N; SizeAreaWB_mm2: 3; Value1: Unknown; U/M: EA; Value: 1000pF; TaMax_C: 125°C; SizeZ_mm: 0.6; SizeX_mm: 1; SizeY_mm: 0.5; AEC Qualified: Y; Cap_F: 1nF; AEC Category: Q200
C14 C18 C22 C25 C59-C61 = CMP-0080610-1: CAP, CERM, 0.1 µF, 25 V,+/- 10%, X7R, AEC-Q200 Grade 1, 0402; Manufacturer: TDK; TaMin_C: -55°C; Polarized: N; SizeAreaWB_mm2: 3; U/M: EA; Value: 0.1uF; TaMax_C: 125°C; SizeZ_mm: 0.6; SizeX_mm: 1; SizeY_mm: 0.5; AEC Qualified: Y; Cap_F: 100nF; AEC Category: Q200
C15 = CMP-0006356-2: CAP, CERM, 0.1 uF, 50 V, +/- 10%, X7R, AEC-Q200 Grade 1, 0402; Manufacturer: MuRata; TaMin_C: -55°C; Polarized: N; SizeAreaWB_mm2: 3; Value1: Unknown; U/M: EA; Value: 0.1uF; TaMax_C: 125°C; SizeZ_mm: 0.6; SizeX_mm: 1; SizeY_mm: 0.5; AEC Qualified: Y; Cap_F: 100nF; AEC Category: Q200
C16 C17 = CMP-0084284-1: CAP, CERM, 2.2 µF, 10 V,+/- 10%, X7R, AEC-Q200 Grade 1, 0603; Manufacturer: MuRata; SizeAreaWB_mm2: 4.68; Polarized: N; AEC Qualified: Y; SizeX_mm: 1.6; SizeZ_mm: 1; SizeY_mm: 0.8; U/M: EA; TaMin_C: -55°C; Value: 2.2uF; AEC Category: Q200; TaMax_C: 125°C; SizeArea_mm2: 1.28
C19-C21 C57 C67 C68 = CMP-0008811-3: CAP, CERM, 22 uF, 10 V, +/- 10%, X7R, AEC-Q200 Grade 1, 1206; Manufacturer: MuRata; SizeX_mm: 3.2; SizeArea_mm2: 5.12; Polarized: N; SizeY_mm: 1.6; TaMin_C: -55°C; SizeZ_mm: 1.8; Cap_Case: 1206; AEC Grade: 1; Value1: Unknown; U/M: EA; AEC Qualified: Y; SizeAreaWB_mm2: 10.92; AEC Category: Q200; Value: 22uF; Cap_F: 22µF; TaMax_C: 125°C
C23 C26 = CMP-0006327-2: CAP, CERM, 0.015 uF, 50 V, +/- 10%, X7R, AEC-Q200 Grade 1, 0402; Manufacturer: TDK; TaMin_C: -55°C; ESR_ohm: 0.2162; Polarized: N; SizeAreaWB_mm2: 3; Value1: 0.2162 ohm; U/M: EA; TaMax_C: 125°C; SizeZ_mm: 0.6; SizeX_mm: 1; SizeY_mm: 0.5; AEC Qualified: Y; Cap_F: 15nF; IRMS_A: 379.389mA; AEC Category: Q200
C24 = CMP-0006310-2: CAP, CERM, 150 pF, 50 V, +/- 5%, C0G/NP0, AEC-Q200 Grade 1, 0402; Manufacturer: TDK; TaMin_C: -55°C; Polarized: N; SizeAreaWB_mm2: 3; Value1: Unknown; U/M: EA; Value: 150pF; TaMax_C: 125°C; SizeZ_mm: 0.6; SizeX_mm: 1; SizeY_mm: 0.5; AEC Qualified: Y; AEC Category: Q200
C27 C65 C69 = CMP-0012661-3: CAP, Tantalum Polymer, 220 uF, 10 V, +/- 20%, 0.025 ohm, AEC-Q200 Grade 1, 7343-31 SMD; Manufacturer: Kemet; TaMin_C: -55°C; ESR_ohm: 25m; Polarized: Y; SizeAreaWB_mm2: 58.59; Value: 220uF; TaMax_C: 125°C; SizeZ_mm: 3.1; SizeX_mm: 7.3; SizeY_mm: 4.3; Cap_Case: 7.3x4.3x3.1mm; SizeArea_mm2: 31.39; CompType: Capacitor; Cap_F: 220µF; IRMS_A: 3A; AEC Grade: 1; AEC Category: Q200
C74 C75 = CMP-0008361-2: CAP, CERM, 0.01 uF, 100 V, +/- 10%, X7R, 0805; Manufacturer: MuRata; TaMin_C: -55°C; Polarized: N; SizeAreaWB_mm2: 6.75; Value1: Unknown; U/M: EA; Value: 0.01uF; TaMax_C: 125°C; SizeZ_mm: 1.45; SizeX_mm: 2; SizeY_mm: 1.25; Cap_Case: 0805; SizeArea_mm2: 2.5; AEC Category: Q200
C102 = CMP-0011185-2: CAP, AL, 47 uF, 50 V, +/- 20%, 0.68 ohm, AEC-Q200 Grade 2, SMD; Manufacturer: Panasonic; TaMin_C: -55°C; ESR_ohm: 0.68; Polarized: Y; SizeAreaWB_mm2: 84.28; U/M: EA; Value: 47uF; TaMax_C: 105°C; SizeZ_mm: 7.7; SizeX_mm: 7.8; SizeY_mm: 6.6; Cap_Case: D8; SizeArea_mm2: 51.48; CompType: Capacitor; Cap_F: 47µF; IRMS_A: 195mA; AEC Grade: 2; AEC Category: Q200
D1 = CMP-0028855-2: Diode, Schottky, 40 V, 3 A, AEC-Q101, SMAF; Manufacturer: Fairchild Semiconductor; Value1: 3A; SizeArea_mm2: 11.75; SizeZ_mm: 1; TJmax_C: 150°C; Vr_V: 40V; SizeX_mm: 4.7; AEC Qualified: Y; SizeY_mm: 2.5; Value2: 0.5V; AEC Category: Q101; Vf_V: 500mV; Value: 40V; Green_REACh: Incomplete; SizeAreaWB_mm2: 19.95; Green_Lifecycle: Not Set
J1 J2 = CMP-0075500-1: as J5 on sheet PMP31252RevA_Input
L1 = CMP-0063436-2: Inductor, Shielded, Powdered Iron, 470 nH, 27 A, 0.00255 ohm, SMD; Manufacturer: Vishay-Dale; PartNumber: IHLP3232DZERR47M01; Isat: 31.5A @ 20% inductance drop; Irms: 25A @ 40C rise; Green_Lifecycle: Not Set; SizeAreaWB_mm2: 111.834; DCR_ohm: 2.62m; Green_REACh: Incomplete; Value1: 0.00262 ohm; Value: 470nH; Imax_A: 25A; SizeZ_mm: 4; SizeX_mm: 8.9; SizeY_mm: 8.26; SizeArea_mm2: 73.514; AEC Category: Q200
L2 = CMP-0092349-1: Shielded Power Inductors 1.8uH, AEC Qualified SMD; Manufacturer: Coilcraft; Part Number: XGL6060-472MEC; Isat: 5.1A; AEC Grade: Grade 1; Test Frequency: 1MHz; Irms: 13.5A; SizeZ_mm: 6.1mm; TaMax_C: +125°C; Tolerance_%: 20%; DCR_ohm: 10.1m; Self Resonant Frequency: 19MHz; TaMin_C: -40°C; AEC Qualified: Yes; Material: Composite; Ind_H: 4.7µH; Value: 4.7uH; Shrouded: true
L3 L6 = CMP-0097455-1: Shielded Power Inductors 3.3uH 22A 5.7mOhm; PartNumber: XGL1060-332MEC; Manufacturer: Coilcraft; Isat: 10.9A; DCR_ohm: 5.7m; Ind_H: 3.3µH; Self Resonant Frequency: 21MHz; AEC Grade: Grade 1; SizeZ_mm: 6mm; Tolerance_%: 20%; TaMax_C: +125°C; AEC Qualified: Yes; TaMin_C: -40°C; Test Frequency: 1MHz; Material: Composite; Shrouded: true
NT1-NT3 = CMP-0078142-6: Single point connection between nets.
Q1 Q2 = CMP-0086959-1: Trans Mosfet N-ch 40V 120A 8-PIN Pg-tdson T/R; Manufacturer: Infineon; PartNumber: IAUC120N04S6N009ATMA1; SizeZ_mm: 1.1mm; Rdson45_ohm: 750µ; QgTyp_nC: 76nC @ 10V; Vgs_V: 20V; AEC Qualified: Yes; ChMode: False
R1 = CMP-0022003-4: RES, 10.0, 1%, 0.1 W, AEC-Q200 Grade 0, 0603; Manufacturer: Vishay-Dale; Power_W: 100mW; TempCo: 100 ppm/C; Value_Code: 10R0; Value: 10.0; EIA_Code: E96; Res_ohm: 10; SizeX_mm: 1.6; SizeY_mm: 0.8; SizeZ_mm: 1; Value2: 0.1W; SizeArea_mm2: 1.28; AEC Qualified: Y; VDC_V: 75V; AEC Category: Q200; AEC Grade: 0
R2 = CMP-0026790-1: RES, 1.00 k, 0.1%, 0.063 W, AEC-Q200 Grade 0, 0402; Manufacturer: Panasonic; Power_W: 63mW; TempCo: 15 ppm/C; Value_Code: 1k00; U/M: EA; Value: 1.00k; EIA_Code: E192; Res_ohm: 1k; SizeX_mm: 1; SizeY_mm: 0.5; SizeZ_mm: 0.6; Value2: 0.063W; AEC Qualified: Y; VDC_V: 50V; AEC Grade: 0; AEC Category: Q200
R3 R19 = CMP-0026702-1: RES, 49.9 k, 1%, 0.1 W, AEC-Q200 Grade 0, 0402; Manufacturer: Panasonic; Power_W: 100mW; TempCo: 100 ppm/C; Value_Code: 49k9; U/M: EA; Value: 49.9k; EIA_Code: E96; SizeX_mm: 1; SizeY_mm: 0.5; SizeZ_mm: 0.6; Value2: 0.1W; AEC Qualified: Y; VDC_V: 50V; AEC Grade: 0; AEC Category: Q200
R4 = CMP-0022306-4: RES, 2.21, 1%, 0.1 W, AEC-Q200 Grade 0, 0603; Manufacturer: Vishay-Dale; Power_W: 100mW; TempCo: 100 ppm/C; Value_Code: 2R21; Value: 2.21; EIA_Code: E96; SizeX_mm: 1.6; SizeY_mm: 0.8; SizeZ_mm: 1; Value2: 0.1W; SizeArea_mm2: 1.28; AEC Qualified: Y; VDC_V: 75V; AEC Category: Q200; AEC Grade: 0
R5 R33 = CMP-0025950-3: as R64 on sheet PMP31252RevA_Input
R6 = CMP-0097669-1: 3 mOhms ±1% 2W Chip Resistor Wide 2010 (5025 Metric), 1020 Anti-Sulfur, Automotive AEC-Q200, Current Sense, Moisture Resistant, Pulse Withstanding Metal Element; Manufacturer: Vishay; AEC Qualified: Yes; Res_ohm: 3m; AEC Grade: Grade 0; Value: 3m; TempCo: 50ppm/°C; SizeZ_mm: 0.762mm
R7 = CMP-0026925-3: RES, 3.0, 5%, 0.063 W, AEC-Q200 Grade 0, 0402; Manufacturer: Vishay-Dale; Power_W: 63mW; TempCo: 200 ppm/C; Value_Code: 3R00; Value: 3.0; EIA_Code: E24; Res_ohm: 3; SizeX_mm: 1; SizeY_mm: 0.5; SizeZ_mm: 0.6; Value2: 0.063W; AEC Qualified: Y; VDC_V: 50V; AEC Category: Q200; AEC Grade: 0
R8 R9 = CMP-0025697-4: RES, 0, 5%, 0.1 W, AEC-Q200 Grade 0, 0603; Manufacturer: Vishay-Dale; Power_W: 100mW; TempCo: 200 ppm/C; Value_Code: 0000; Value: 0; EIA_Code: E24; SizeX_mm: 1.6; SizeY_mm: 0.8; SizeZ_mm: 1; Value2: 0.1W; SizeArea_mm2: 1.28; AEC Qualified: Y; VDC_V: 75V; AEC Category: Q200
R10 R11 R15 R17 R21 R22 R25 R35 = CMP-0026992-3: as R71 on sheet PMP31252RevA_Input
R12 R23 = CMP-0026703-1: as R58 on sheet PMP31252RevA_Input
R13 = CMP-0026196-2: RES, 24.9 k, 1%, 0.063 W, AEC-Q200 Grade 0, 0402; Manufacturer: Vishay-Dale; Power_W: 63mW; TempCo: 100 ppm/C; Value_Code: 24k9; Value: 24.9k; EIA_Code: E96; SizeX_mm: 1; SizeY_mm: 0.5; SizeZ_mm: 0.6; Value2: 0.063W; AEC Qualified: Y; VDC_V: 50V; AEC Category: Q200; AEC Grade: 0
R14 = CMP-0026883-3: RES, 24 k, 5%, 0.063 W, AEC-Q200 Grade 0, 0402; Manufacturer: Vishay-Dale; Power_W: 63mW; TempCo: 200 ppm/C; Value_Code: 24k0; Value: 24k; EIA_Code: E24; SizeX_mm: 1; SizeY_mm: 0.5; SizeZ_mm: 0.6; Value2: 0.063W; AEC Qualified: Y; VDC_V: 50V; AEC Category: Q200; AEC Grade: 0
R16 = CMP-0026395-2: RES, 47.5 k, 1%, 0.063 W, AEC-Q200 Grade 0, 0402; Manufacturer: Vishay-Dale; Power_W: 63mW; TempCo: 100 ppm/C; Value_Code: 47k5; Value: 47.5k; EIA_Code: E96; SizeX_mm: 1; SizeY_mm: 0.5; SizeZ_mm: 0.6; Value2: 0.063W; AEC Qualified: Y; VDC_V: 50V; AEC Category: Q200; AEC Grade: 0
R18 R67 = CMP-0025978-3: RES, 11.8 k, 1%, 0.063 W, AEC-Q200 Grade 0, 0402; Manufacturer: Vishay-Dale; Power_W: 63mW; TempCo: 100 ppm/C; Value_Code: 11k8; Value: 11.8k; EIA_Code: E96; SizeX_mm: 1; SizeY_mm: 0.5; SizeZ_mm: 0.6; Value2: 0.063W; AEC Qualified: Y; VDC_V: 50V; AEC Category: Q200; AEC Grade: 0
R20 = CMP-0026535-2: RES, 71.5 k, 1%, 0.063 W, AEC-Q200 Grade 0, 0402; Manufacturer: Vishay-Dale; Power_W: 63mW; TempCo: 100 ppm/C; Value_Code: 71k5; Value: 71.5k; EIA_Code: E96; SizeX_mm: 1; SizeY_mm: 0.5; SizeZ_mm: 0.6; Value2: 0.063W; AEC Qualified: Y; VDC_V: 50V; AEC Category: Q200; AEC Grade: 0
R24 = CMP-0026619-3: RES, 9.09 k, 1%, 0.063 W, AEC-Q200 Grade 0, 0402; Manufacturer: Vishay-Dale; VDC_V: 50V; Value2: 0.063W; Power_W: 63mW; AEC Qualified: Y; SizeZ_mm: 0.6; TempCo: 100 ppm/C; SizeArea_mm2: 0.5; SizeX_mm: 1; Value: 9.09k; Value_Code: 9k09; AEC Category: Q200; AEC Grade: 0; EIA_Code: E96
R26-R29 = CMP-0017276-1: RES, 0, 1%, 0.25 W, 1206; Manufacturer: State of the Art; Power_W: 250mW; TempCo: 25 ppm/C; U/M: EA; Value: 0; SizeX_mm: 3.2; SizeY_mm: 1.55; SizeZ_mm: 0.84; Value2: 0.25W; SizeArea_mm2: 4.96; AEC Qualified: N; AEC Category: Q200
R30 R31 = CMP-0017853-2: RES, 110, 1%, 0.25 W, 1206; Manufacturer: Yageo America; Power_W: 250mW; TempCo: 100 ppm/C; Value_Code: 110R; U/M: EA; Value: 110; EIA_Code: E96; SizeX_mm: 3.2; SizeY_mm: 1.6; SizeZ_mm: 1.35; Value2: 0.25W; SizeArea_mm2: 5.12; VDC_V: 200V; AEC Category: Q200
R69 = CMP-0022716-3: RES, 0.47, 1%, 0.1 W, AEC-Q200 Grade 0, 0603; Manufacturer: Panasonic; Power_W: 100mW; TempCo: 300 ppm/C; Value_Code: R470; Value: 0.47; EIA_Code: E96; SizeX_mm: 1.6; SizeY_mm: 0.8; SizeZ_mm: 1; Value2: 0.1W; SizeArea_mm2: 1.28; AEC Qualified: Y; AEC Category: Q200; AEC Grade: 0; SizeAreaWB_mm2: 4.68
R70 = CMP-0021843-3: RES, 0.56, 1%, 0.125 W, AEC-Q200 Grade 0, 0805; Manufacturer: Panasonic; Power_W: 125mW; TempCo: 250 ppm/C; Value_Code: R560; Value: 0.56; EIA_Code: E96; SizeX_mm: 2; SizeY_mm: 1.25; SizeZ_mm: 1.45; Value2: 0.125W; SizeArea_mm2: 2.5; AEC Qualified: Y; AEC Category: Q200; AEC Grade: 0; SizeAreaWB_mm2: 6.75
T1 T2 = CMP-0055442-1: as T5 on sheet PMP31252RevA_Input
TP1 TP8 TP10 = CMP-0055137-2: Test Point, Miniature, Red, TH; Manufacturer: Keystone Electronics; Green_REACh: Passed; Green_Lifecycle: Active; ContactFinish: Silver; CNHeader: FALSE; CT: TRUE
TP2 = CMP-0055141-2: Test Point, Miniature, Yellow, TH; Manufacturer: Keystone Electronics; CT: TRUE; ContactFinish: Silver; Green_Lifecycle: Active; CNHeader: FALSE; Green_REACh: Passed
TP3 TP9 TP11 = CMP-0055138-2: Test Point, Miniature, Black, TH; Manufacturer: Keystone Electronics; ContactFinish: Silver; CNHeader: FALSE; Green_Lifecycle: Active; Green_REACh: Passed; CT: TRUE
U1 = CMP-0092804-1: Automotive Synchronous Buck DC/DC Controller with Ultra-Low IQ, Adjustable, 0.8-36V, VQFN24; Manufacturer: Texas Instruments; Max Duty Cycle: 100%; Standoff Height: 0mm; Number Of Outputs: 1; Switching Frequency: 100-2200kHz; Max Supply Voltage: 42V; TaMin_C: -40°C; Output Type: AdjustableProgrammable; SizeZ_mm: 1mm; Min Supply Voltage: 3.5V; TaMax_C: +125°C; TJmax_C: +150°C; AEC Grade: Grade 1; AEC Qualified: Yes

## Sheet PMP31252RevA_S.SchDoc
size A3; Date: Not shown in title block; ApprovedBy: Not shown in title block; CheckedBy: Not shown in title block; Author: Not shown in title block; CompanyName: Not shown in title block; Engineer: Not shown in title block; Organization: Not shown in title block; Address1: Not shown in title block; Address2: Not shown in title block; Address3: Not shown in title block; Address4: Not shown in title block; DocumentNumber: 1; Revision: Use project parameter SCH_Rev; SheetNumber: 3; SheetTotal: 3; PageSetup: Record=PageOptions¦CenterHorizontal=True¦CenterVertical=True¦PrintScale=0.69¦XCorrection=1.00¦YCorrection=1.00¦PrintKind=0¦BorderSize=5000000¦LeftOffset=0¦BottomOffset=0¦Orientation=2¦PaperLength=1000¦PaperWidth=1000¦Scale=100¦PaperSource=15¦PrintQuality=600¦MediaType=1¦DitherType=10¦PaperKind=Letter¦PrintScaleMode=1
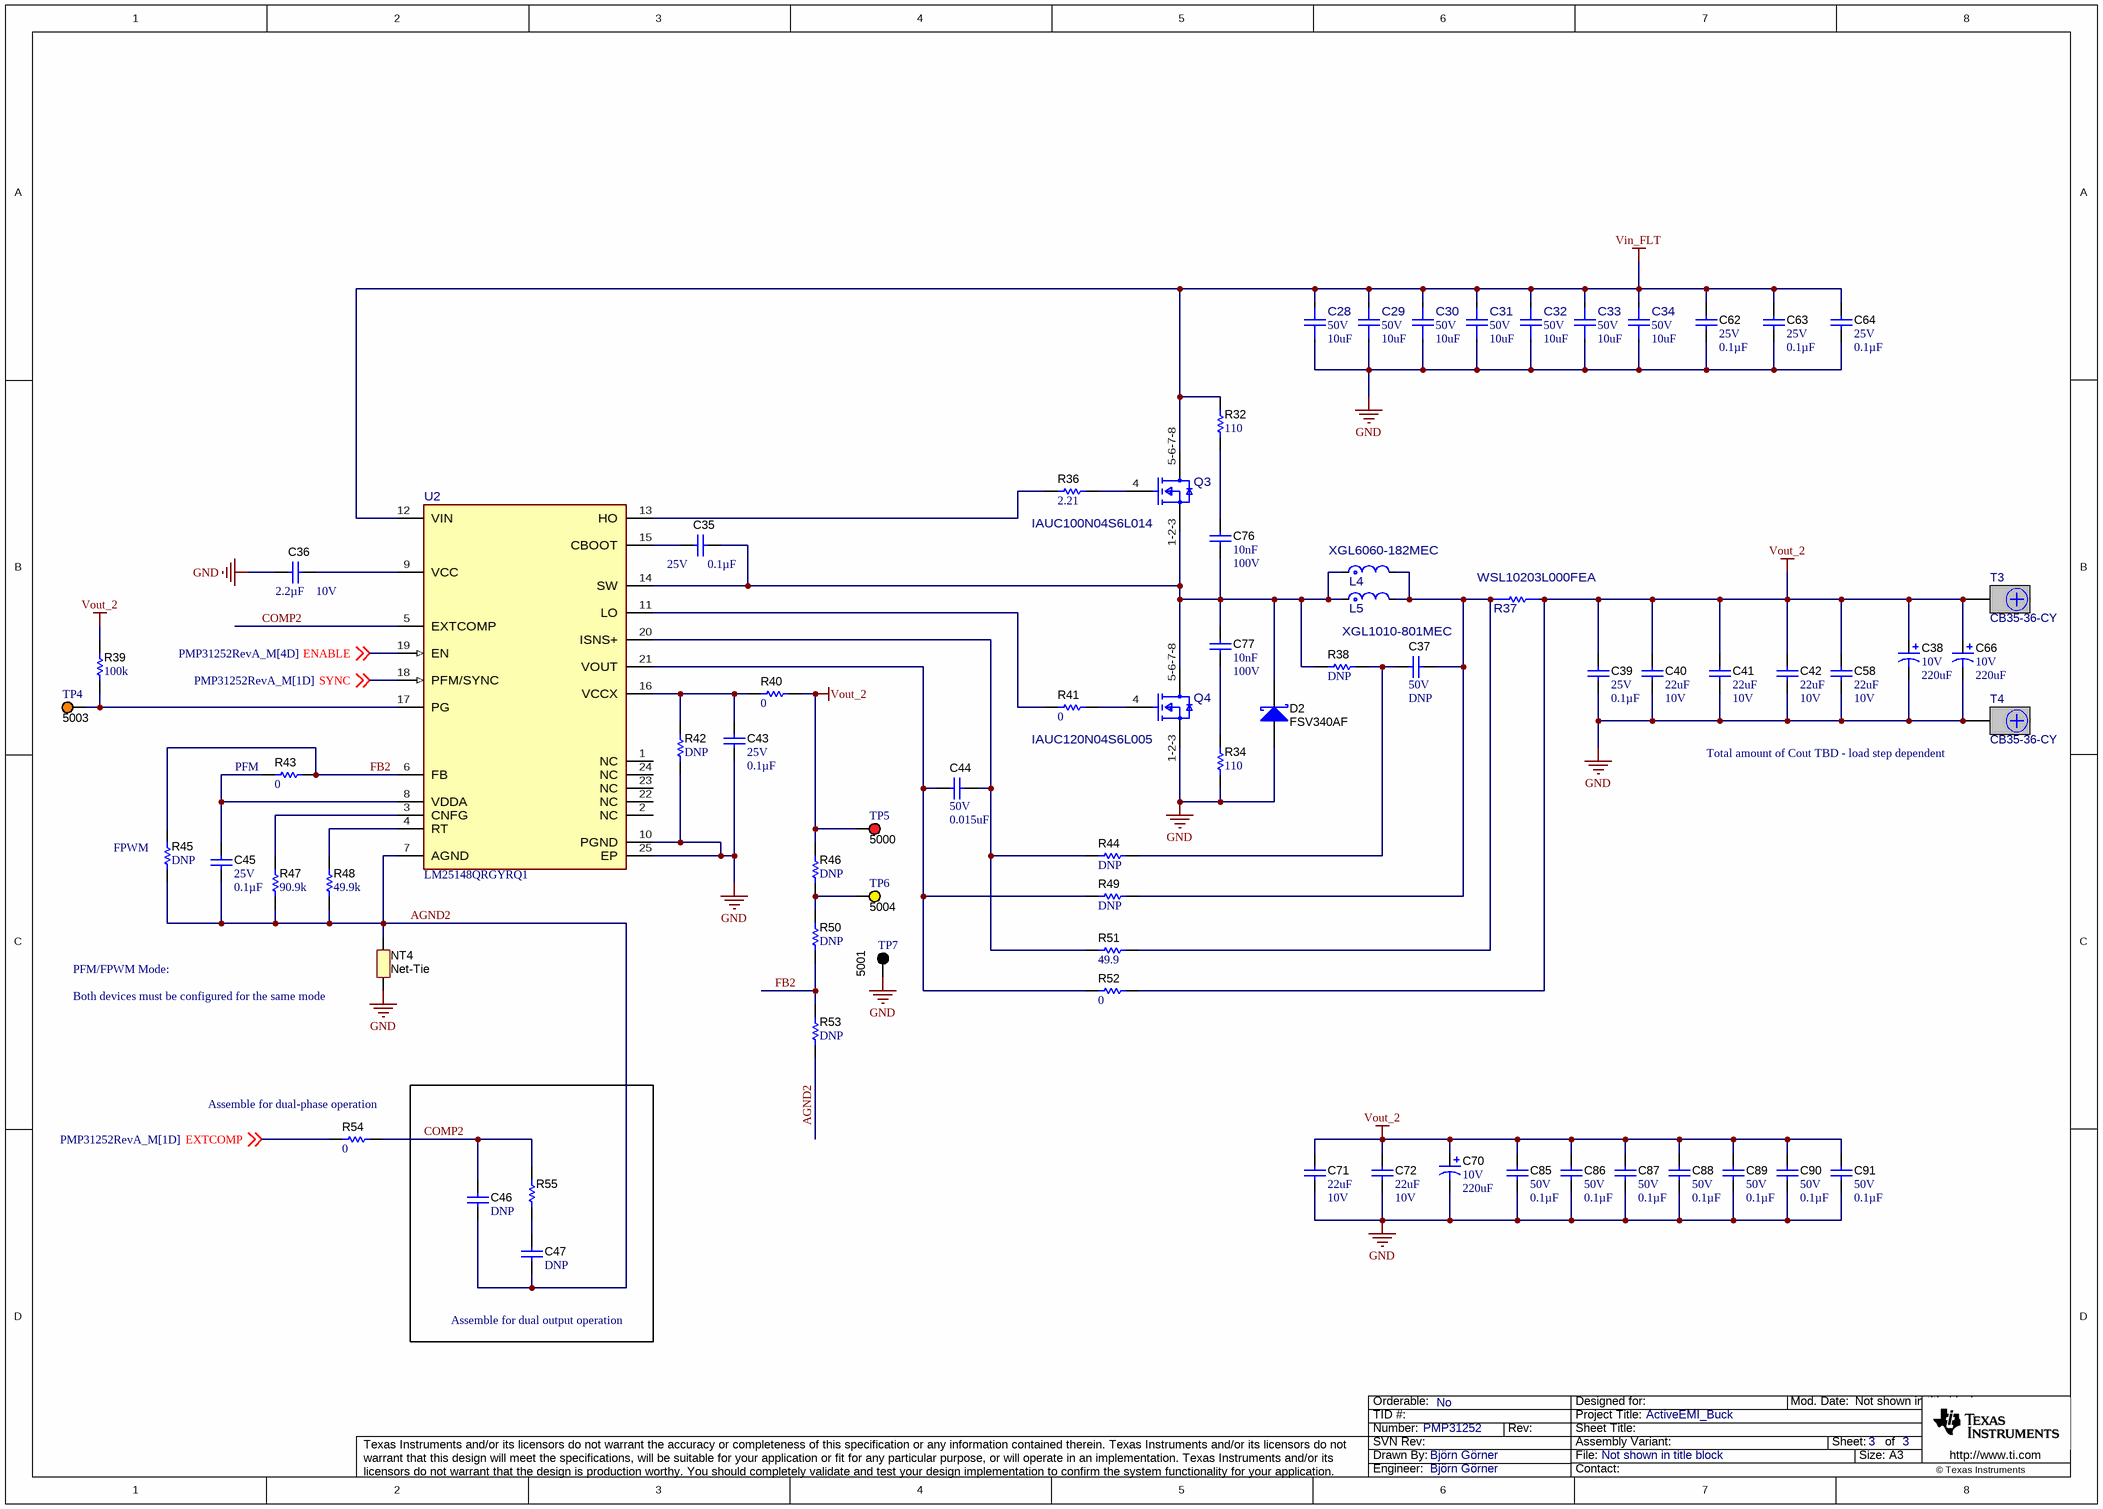
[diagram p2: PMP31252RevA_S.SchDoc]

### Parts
C28  VDC_V: 50V  ValueDisplayed: 10uF  [FP-GCM32EC71H106KA03L_1210-MFG]  (hidden comment: GCM32EC71H106KA03L)
C29  VDC_V: 50V  ValueDisplayed: 10uF  [FP-GCM32EC71H106KA03L_1210-MFG]  (hidden comment: GCM32EC71H106KA03L)
C30  VDC_V: 50V  ValueDisplayed: 10uF  [FP-GCM32EC71H106KA03L_1210-MFG]  (hidden comment: GCM32EC71H106KA03L)
C31  VDC_V: 50V  ValueDisplayed: 10uF  [FP-GCM32EC71H106KA03L_1210-MFG]  (hidden comment: GCM32EC71H106KA03L)
C32  VDC_V: 50V  ValueDisplayed: 10uF  [FP-GCM32EC71H106KA03L_1210-MFG]  (hidden comment: GCM32EC71H106KA03L)
C33  VDC_V: 50V  ValueDisplayed: 10uF  [FP-GCM32EC71H106KA03L_1210-MFG]  (hidden comment: GCM32EC71H106KA03L)
C34  VDC_V: 50V  ValueDisplayed: 10uF  [FP-GCM32EC71H106KA03L_1210-MFG]  (hidden comment: GCM32EC71H106KA03L)
C35  VDC_V: 25V  ValueDisplayed: 0.1µF  [0402]  (hidden comment: CGA2B3X7R1E104K050BB)
C36  Cap_F: 2.2µF  VDC_V: 10V  [0603]  (hidden comment: GRM188R71A225KE15J)
C37  VDC_V: 50V  ValueDisplayed: DNP  [0402]  (hidden comment: GCM155R71H104KE02D)
C38  VDC_V: 10V  ValueDisplayed: 220uF  [7343-31]  (hidden comment: T598D227M010ATE025)
C39  VDC_V: 25V  ValueDisplayed: 0.1µF  [0402]  (hidden comment: CGA2B3X7R1E104K050BB)
C40  ValueDisplayed: 22uF  VDC_V: 10V  [1206_180]  (hidden comment: GCM31CR71A226KE02L)
C41  ValueDisplayed: 22uF  VDC_V: 10V  [1206_180]  (hidden comment: GCM31CR71A226KE02L)
C42  ValueDisplayed: 22uF  VDC_V: 10V  [1206_180]  (hidden comment: GCM31CR71A226KE02L)
C43  VDC_V: 25V  ValueDisplayed: 0.1µF  [0402]  (hidden comment: CGA2B3X7R1E104K050BB)
C44  VDC_V: 50V  ValueDisplayed: 0.015uF  [0402]  (hidden comment: CGA2B3X7R1H153K050BB)
C45  VDC_V: 25V  ValueDisplayed: 0.1µF  [0402]  (hidden comment: CGA2B3X7R1E104K050BB)
C46  VDC_V: DNP  [0402]  (hidden comment: CGA2B2C0G1H151J050BA)
C47  VDC_V: DNP  [0402]  (hidden comment: CGA2B3X7R1H153K050BB)
C58  ValueDisplayed: 22uF  VDC_V: 10V  [1206_180]  (hidden comment: GCM31CR71A226KE02L)
C62  VDC_V: 25V  ValueDisplayed: 0.1µF  [0402]  (hidden comment: CGA2B3X7R1E104K050BB)
C63  VDC_V: 25V  ValueDisplayed: 0.1µF  [0402]  (hidden comment: CGA2B3X7R1E104K050BB)
C64  VDC_V: 25V  ValueDisplayed: 0.1µF  [0402]  (hidden comment: CGA2B3X7R1E104K050BB)
C66  VDC_V: 10V  ValueDisplayed: 220uF  [7343-31]  (hidden comment: T598D227M010ATE025)
C70  VDC_V: 10V  ValueDisplayed: 220uF  [7343-31]  (hidden comment: T598D227M010ATE025)
C71  ValueDisplayed: 22uF  VDC_V: 10V  [1206_180]  (hidden comment: GCM31CR71A226KE02L)
C72  ValueDisplayed: 22uF  VDC_V: 10V  [1206_180]  (hidden comment: GCM31CR71A226KE02L)
C76  Cap_F: 10nF  VDC_V: 100V  [0805_HV]  (hidden comment: GRM21BR72A103KA01L)
C77  Cap_F: 10nF  VDC_V: 100V  [0805_HV]  (hidden comment: GRM21BR72A103KA01L)
C85  VDC_V: 50V  ValueDisplayed: 0.1µF  [0603]  (hidden comment: CGA3E3X8R1H104K080AE)
C86  VDC_V: 50V  ValueDisplayed: 0.1µF  [0603]  (hidden comment: CGA3E3X8R1H104K080AE)
C87  VDC_V: 50V  ValueDisplayed: 0.1µF  [0603]  (hidden comment: CGA3E3X8R1H104K080AE)
C88  VDC_V: 50V  ValueDisplayed: 0.1µF  [0603]  (hidden comment: CGA3E3X8R1H104K080AE)
C89  VDC_V: 50V  ValueDisplayed: 0.1µF  [0603]  (hidden comment: CGA3E3X8R1H104K080AE)
C90  VDC_V: 50V  ValueDisplayed: 0.1µF  [0603]  (hidden comment: CGA3E3X8R1H104K080AE)
C91  VDC_V: 50V  ValueDisplayed: 0.1µF  [0603]  (hidden comment: CGA3E3X8R1H104K080AE)
D2  FSV340AF  [SMAF]
L4  XGL6060-182MEC  [FP-XGL6060-472MEC_SMT2_6MM51_6MM71-MFG]
L5  XGL1010-801MEC  [FP-XGL1060-332MEC_SMT2_10MM0_11MM3-MFG]
NT4  Net-Tie  [Net-Tie_10milWide_30milLong]  (net tie, no BOM)
Q3  IAUC100N04S6L014  [FP-IAUC120N04S6N009ATMA1_TDSON8-MFG]
Q4  IAUC120N04S6L005  [FP-IAUC120N04S6N009ATMA1_TDSON8-MFG]
R32  ValueDisplayed: 110  [1206]  (hidden comment: RC1206FR-07110RL)
R34  ValueDisplayed: 110  [1206]  (hidden comment: RC1206FR-07110RL)
R36  ValueDisplayed: 2.21  [0603]  (hidden comment: CRCW06032R21FKEA)
R37  WSL10203L000FEA  [FP-WSL10203L000FEA_1020-MFG]
R38  ValueDisplayed: DNP  [0603]  (hidden comment: CRCW06030000Z0EA)
R39  ValueDisplayed: 100k  [0402]  (hidden comment: RMCF0402FT100K)
R40  ValueDisplayed: 0  [0402]  (hidden comment: ERJ-2GE0R00X)
R41  ValueDisplayed: 0  [0603]  (hidden comment: CRCW06030000Z0EA)
R42  ValueDisplayed: DNP  [0402]  (hidden comment: ERJ-2GE0R00X)
R43  ValueDisplayed: 0  [0402]  (hidden comment: ERJ-2GE0R00X)
R44  ValueDisplayed: DNP  [0402]  (hidden comment: ERJ-2GE0R00X)
R45  ValueDisplayed: DNP  [0402]  (hidden comment: ERJ-2GE0R00X)
R46  ValueDisplayed: DNP  [0402]  (hidden comment: ERJ-2RKF49R9X)
R47  ValueDisplayed: 90.9k  [0402]  (hidden comment: CRCW040290K9FKED)
R48  ValueDisplayed: 49.9k  [0402]  (hidden comment: ERJ-2RKF4992X)
R49  ValueDisplayed: DNP  [0402]  (hidden comment: ERJ-2GE0R00X)
R50  ValueDisplayed: DNP  [0402]  (hidden comment: CRCW040224K9FKED)
R51  ValueDisplayed: 49.9  [0402]  (hidden comment: ERJ-2RKF49R9X)
R52  ValueDisplayed: 0  [0402]  (hidden comment: ERJ-2GE0R00X)
R53  ValueDisplayed: DNP  [0402]  (hidden comment: CRCW040224K9FKED)
R54  ValueDisplayed: 0  [0402]  (hidden comment: ERJ-2GE0R00X)
R55  ERJ-2RKF2401X  [0402]  (value not drawn)
T3  CB35-36-CY  [CB35-36-CY]
T4  CB35-36-CY  [CB35-36-CY]
TP4  5003  [Keystone5003]
TP5  5000  [Keystone5000]
TP6  5004  [Keystone5004]
TP7  5001  [Keystone5001]
U2  LM25148QRGYRQ1  [RGY0024E-MFG]

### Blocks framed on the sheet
Assemble for dual output operation: C46 C47 R55

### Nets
GND: C28.1 C29.1 C30.1 C31.1 C32.1 C33.1 C34.1 C36.1 C38.2(-) C39.2 C40.2 C41.2 C42.2 C43.2 C58.2 C62.2 C63.2 C64.2 C66.2(-) C70.2(-) C71.2 C72.2 C85.2 C86.2 C87.2 C88.2 C89.2 C90.2 C91.2 D2.2(A) NT4.2 Q4.1-2-3(S) R34.1 R42.1 T4.1 TP7.1 U2.10(PGND) U2.25(EP)
Vin_FLT: C28.2 C29.2 C30.2 C31.2 C32.2 C33.2 C34.2 C62.1 C63.1 C64.1 Q3.5-6-7-8(D) R32.2 U2.12(VIN)
Vout_2: C38.1(+) C39.1 C40.1 C41.1 C42.1 C58.1 C66.1(+) C70.1(+) C71.1 C72.1 C85.1 C86.1 C87.1 C88.1 C89.1 C90.1 C91.1 R37.2 R39.2 R40.2 R46.2 R52.2 T3.1 TP5.1
AGND2: C45.2 C46.2 C47.2 NT4.1 R45.1 R47.1 R48.1 R53.2 U2.7(AGND)
COMP2: C46.1 R54.2 R55.2 U2.5(EXTCOMP)
ENABLE: U2.19(EN) ; off-sheet ENABLE
EXTCOMP: R54.1 ; off-sheet EXTCOMP
FB2: R43.2 R45.2 R50.2 R53.1 U2.6(FB)
SYNC: U2.18(PFM/SYNC) ; off-sheet SYNC
NetC35_1: C35.1 C76.2 C77.1 D2.1(K) L4.1 L5.1 Q3.1-2-3(S) Q4.5-6-7-8(D) R38.1 U2.14(SW)
NetC35_2: C35.2 U2.15(CBOOT)
NetC36_2: C36.2 U2.9(VCC)
NetC37_1: C37.1 L4.2 L5.2 R37.1 R49.2 R51.2
NetC37_2: C37.2 R38.2 R44.2
NetC43_1: C43.1 R40.1 R42.2 U2.16(VCCX)
NetC44_1: C44.1 R44.1 R51.1 U2.20(ISNS+)
NetC44_2: C44.2 R49.1 R52.1 U2.21(VOUT)
NetC45_1: C45.1 R43.1 U2.8(VDDA)
NetC47_1: C47.1 R55.1
NetC76_1: C76.1 R32.1
NetC77_2: C77.2 R34.2
NetQ3_4: Q3.4(G) R36.2
NetQ4_4: Q4.4(G) R41.2
NetR36_1: R36.1 U2.13(HO)
NetR39_1: R39.1 TP4.1 U2.17(PG)
NetR41_1: R41.1 U2.11(LO)
NetR46_1: R46.1 R50.1 TP6.1
NetR47_2: R47.2 U2.3(CNFG)
NetR48_2: R48.2 U2.4(RT)

Not connected (* = marked no-connect by the designer): U2 1(NC) 2(NC) 22(NC) 23(NC) 24(NC)

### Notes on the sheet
- (near R43) PFM
- (near T4) Total amount of Cout TBD - load step dependent
- (near R45) FPWM
- PFM/FPWM Mode:
- (near NT4) Both devices must be configured for the same mode
- (near R54) Assemble for dual-phase operation

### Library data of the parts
C28-C34 = CMP-0092251-1: as C2 on sheet PMP31252RevA_M
C35 C39 C43 C45 C62-C64 = CMP-0080610-1: as C14 on sheet PMP31252RevA_M
C36 = CMP-0084284-1: as C16 on sheet PMP31252RevA_M
C37 = CMP-0006356-2: as C15 on sheet PMP31252RevA_M
C38 C66 C70 = CMP-0012661-3: as C27 on sheet PMP31252RevA_M
C40-C42 C58 C71 C72 = CMP-0008811-3: as C19 on sheet PMP31252RevA_M
C44 = CMP-0006327-2: as C23 on sheet PMP31252RevA_M
C46 = CMP-0006310-2: CAP, CERM, 150 pF, 50 V, +/- 5%, C0G/NP0, AEC-Q200 Grade 1, 0402; Manufacturer: TDK; TaMin_C: -55°C; Polarized: N; SizeAreaWB_mm2: 3; Value1: Unknown; U/M: EA; Value: 150pF; TaMax_C: 125°C; SizeZ_mm: 0.6; SizeX_mm: 1; SizeY_mm: 0.5; Value2: 50V; AEC Qualified: Y; AEC Category: Q200
C47 = CMP-0006327-2: CAP, CERM, 0.015 uF, 50 V, +/- 10%, X7R, AEC-Q200 Grade 1, 0402; Manufacturer: TDK; TaMin_C: -55°C; ESR_ohm: 0.2162; Polarized: N; SizeAreaWB_mm2: 3; Value1: 0.2162 ohm; U/M: EA; TaMax_C: 125°C; SizeZ_mm: 0.6; SizeX_mm: 1; SizeY_mm: 0.5; Value2: 50V; AEC Qualified: Y; Cap_F: 15nF; IRMS_A: 379.389mA; AEC Category: Q200
C76 C77 = CMP-0008361-2: as C74 on sheet PMP31252RevA_M
C85-C91 = CMP-0079911-1: as C92 on sheet PMP31252RevA_Input
D2 = CMP-0028855-2: as D1 on sheet PMP31252RevA_M
L4 = CMP-0092349-1: as L2 on sheet PMP31252RevA_M
L5 = CMP-0097455-1: as L3 on sheet PMP31252RevA_M
NT4 = CMP-0078142-6: Single point connection between nets.
Q3 Q4 = CMP-0086959-1: as Q1 on sheet PMP31252RevA_M
R32 R34 = CMP-0017853-2: as R30 on sheet PMP31252RevA_M
R36 = CMP-0022306-4: as R4 on sheet PMP31252RevA_M
R37 = CMP-0097669-1: as R6 on sheet PMP31252RevA_M
R38 R41 = CMP-0025697-4: as R8 on sheet PMP31252RevA_M
R39 = CMP-0026753-1: as R59 on sheet PMP31252RevA_Input
R40 R42-R45 R49 R52 R54 = CMP-0026992-3: as R71 on sheet PMP31252RevA_Input
R46 R51 = CMP-0026703-1: as R58 on sheet PMP31252RevA_Input
R47 = CMP-0026605-2: RES, 90.9 k, 1%, 0.063 W, AEC-Q200 Grade 0, 0402; Manufacturer: Vishay-Dale; Power_W: 63mW; TempCo: 100 ppm/C; Value_Code: 90k9; Value: 90.9k; EIA_Code: E96; SizeX_mm: 1; SizeY_mm: 0.5; SizeZ_mm: 0.6; Value2: 0.063W; AEC Qualified: Y; VDC_V: 50V; AEC Category: Q200; AEC Grade: 0
R48 = CMP-0026702-1: as R3 on sheet PMP31252RevA_M
R50 R53 = CMP-0026196-2: as R13 on sheet PMP31252RevA_M
R55 = CMP-0026685-1: RES, 2.40 k, 1%, 0.1 W, AEC-Q200 Grade 0, 0402; Manufacturer: Panasonic; Power_W: 100mW; TempCo: 100 ppm/C; Value_Code: 2k40; U/M: EA; Value: 2.40k; Res_ohm: 2.4k; SizeX_mm: 1; SizeY_mm: 0.5; SizeZ_mm: 0.6; Value2: 0.1W; AEC Qualified: Y; AEC Grade: 0; AEC Category: Q200
T3 T4 = CMP-0055442-1: as T5 on sheet PMP31252RevA_Input
TP4 = CMP-0055140-2: Test Point, Miniature, Orange, TH; Manufacturer: Keystone Electronics; Green_Lifecycle: Active; ContactFinish: Silver; CNHeader: FALSE; CT: TRUE; Green_REACh: Passed
TP5 = CMP-0055137-2: as TP1 on sheet PMP31252RevA_M
TP6 = CMP-0055141-2: as TP2 on sheet PMP31252RevA_M
TP7 = CMP-0055138-2: as TP3 on sheet PMP31252RevA_M
U2 = CMP-0092804-1: as U1 on sheet PMP31252RevA_M

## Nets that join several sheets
GND: PMP31252RevA_Input (22 pins), PMP31252RevA_M (55 pins), PMP31252RevA_S (38 pins)
Vin_FLT: PMP31252RevA_M (24 pins), PMP31252RevA_S (13 pins)
VIN_PROT: PMP31252RevA_Input (6 pins), PMP31252RevA_M (7 pins)
Vout_2: PMP31252RevA_M (5 pins), PMP31252RevA_S (24 pins)
ENABLE: PMP31252RevA_M (J2.1 R33.1 R35.2 R67.2), PMP31252RevA_S (U2.19)
EXTCOMP: PMP31252RevA_M (C24.1 R14.2 U1.5), PMP31252RevA_S (R54.1)
SYNC: PMP31252RevA_M (U1.17), PMP31252RevA_S (U2.18)

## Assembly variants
STD: not fitted C10 C11 C12 C13 C15 C17 C24 C37 C46 C47 C51 C55 C74 C75 C76 C77 L3 L5 L6 R1 R2 R3 R7 R8 R15 R17 R21 R30 R31 R32 R34 R38 R42 R44 R45 R46 R49 R50 R53 R55 R57 R68 R69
